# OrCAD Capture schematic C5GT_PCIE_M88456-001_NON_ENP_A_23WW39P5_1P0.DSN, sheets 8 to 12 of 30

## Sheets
8 Clocks & Osc.: size B
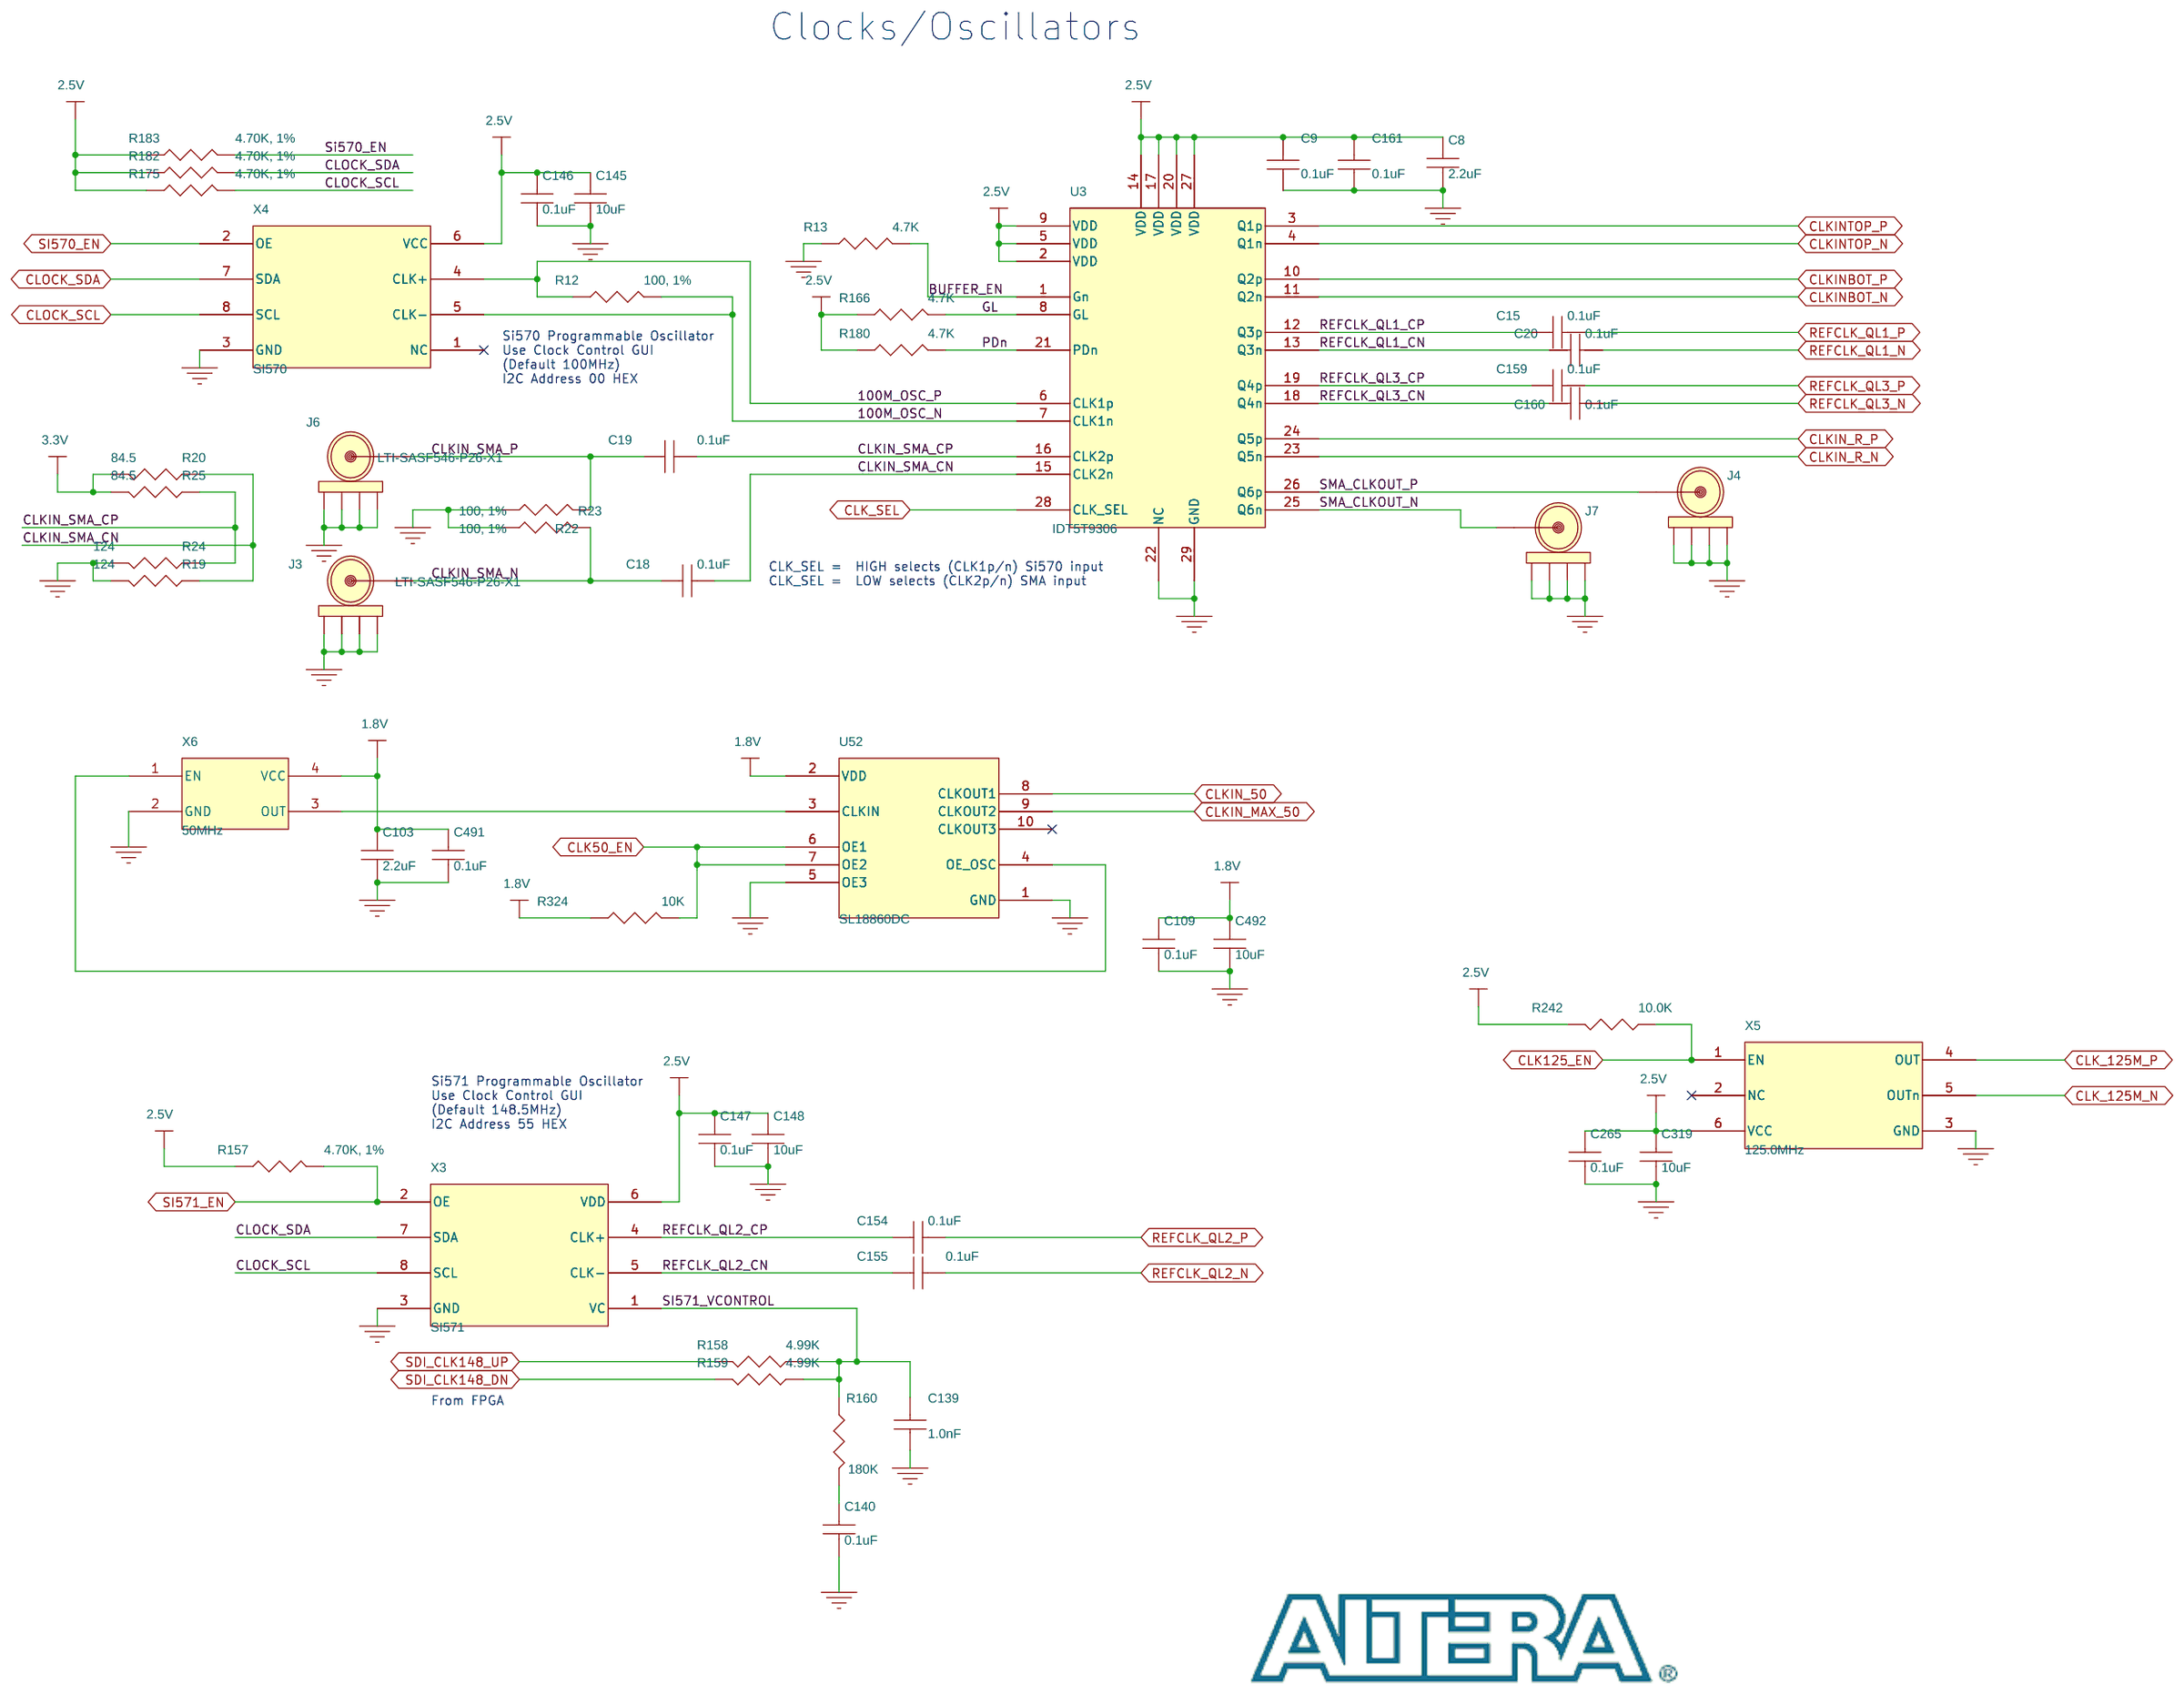
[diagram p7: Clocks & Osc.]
9 Cycone V GT Clks: size B
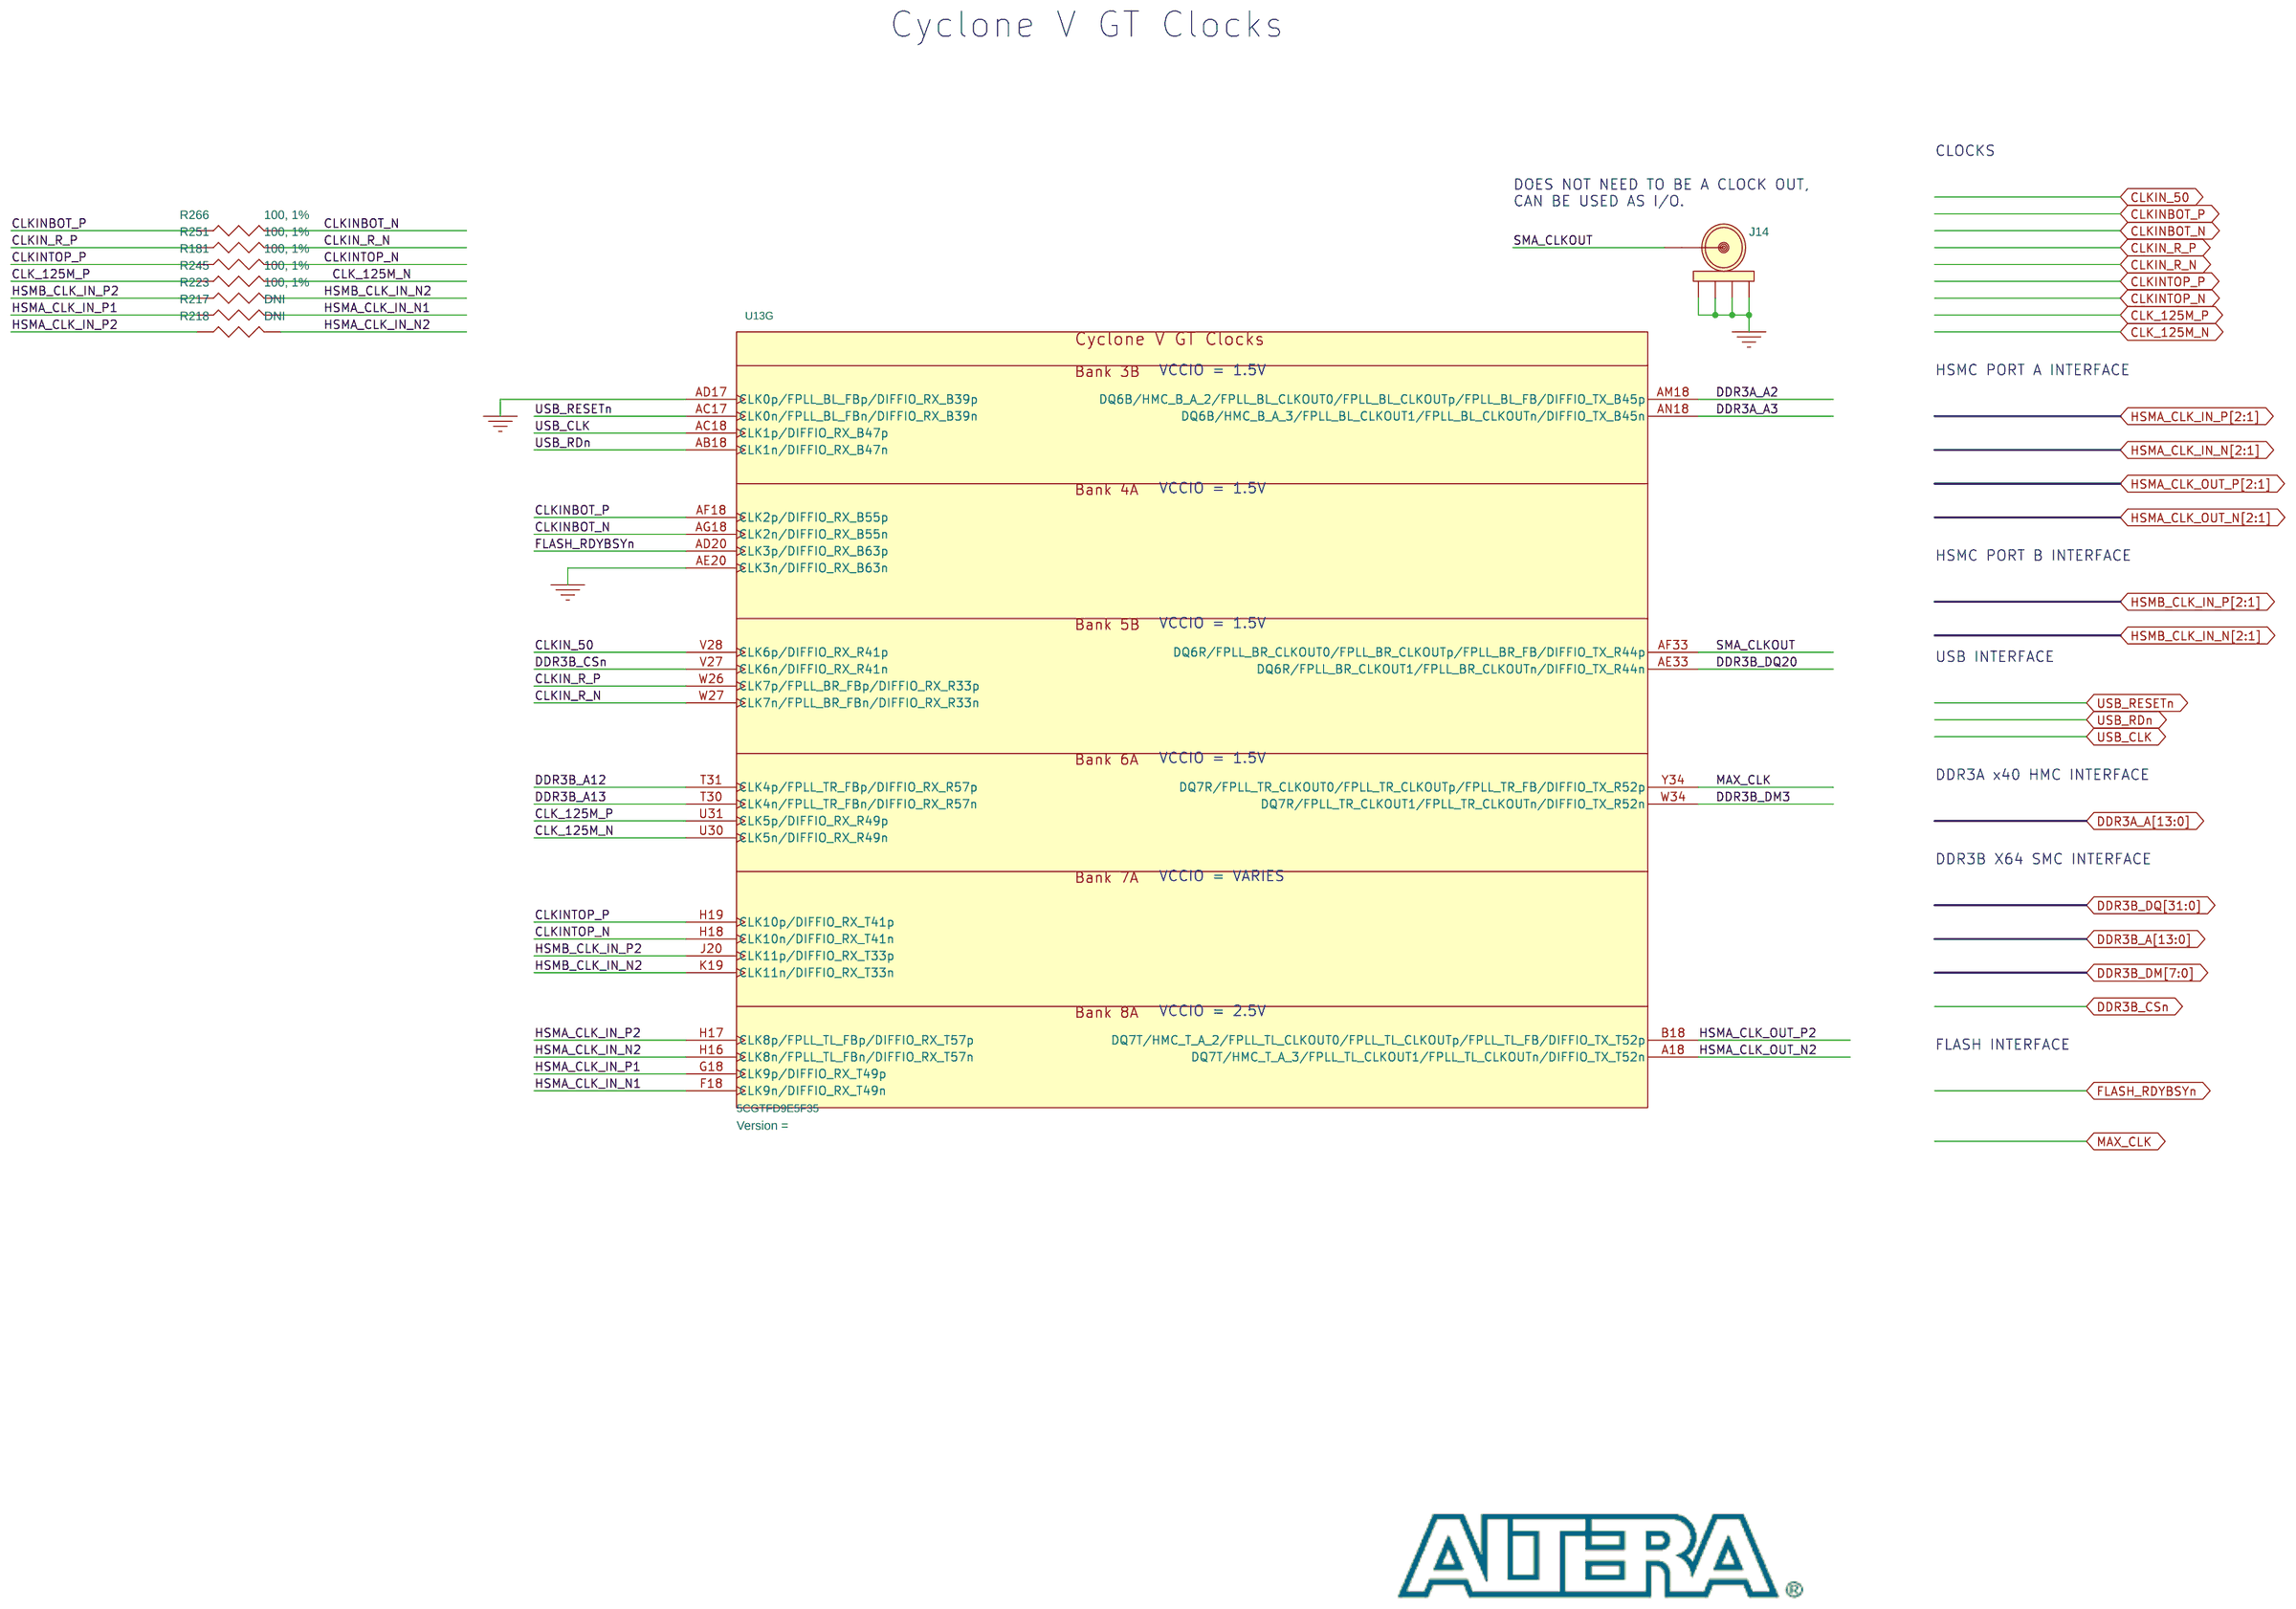
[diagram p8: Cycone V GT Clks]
10 Cycone V GT Config: size B
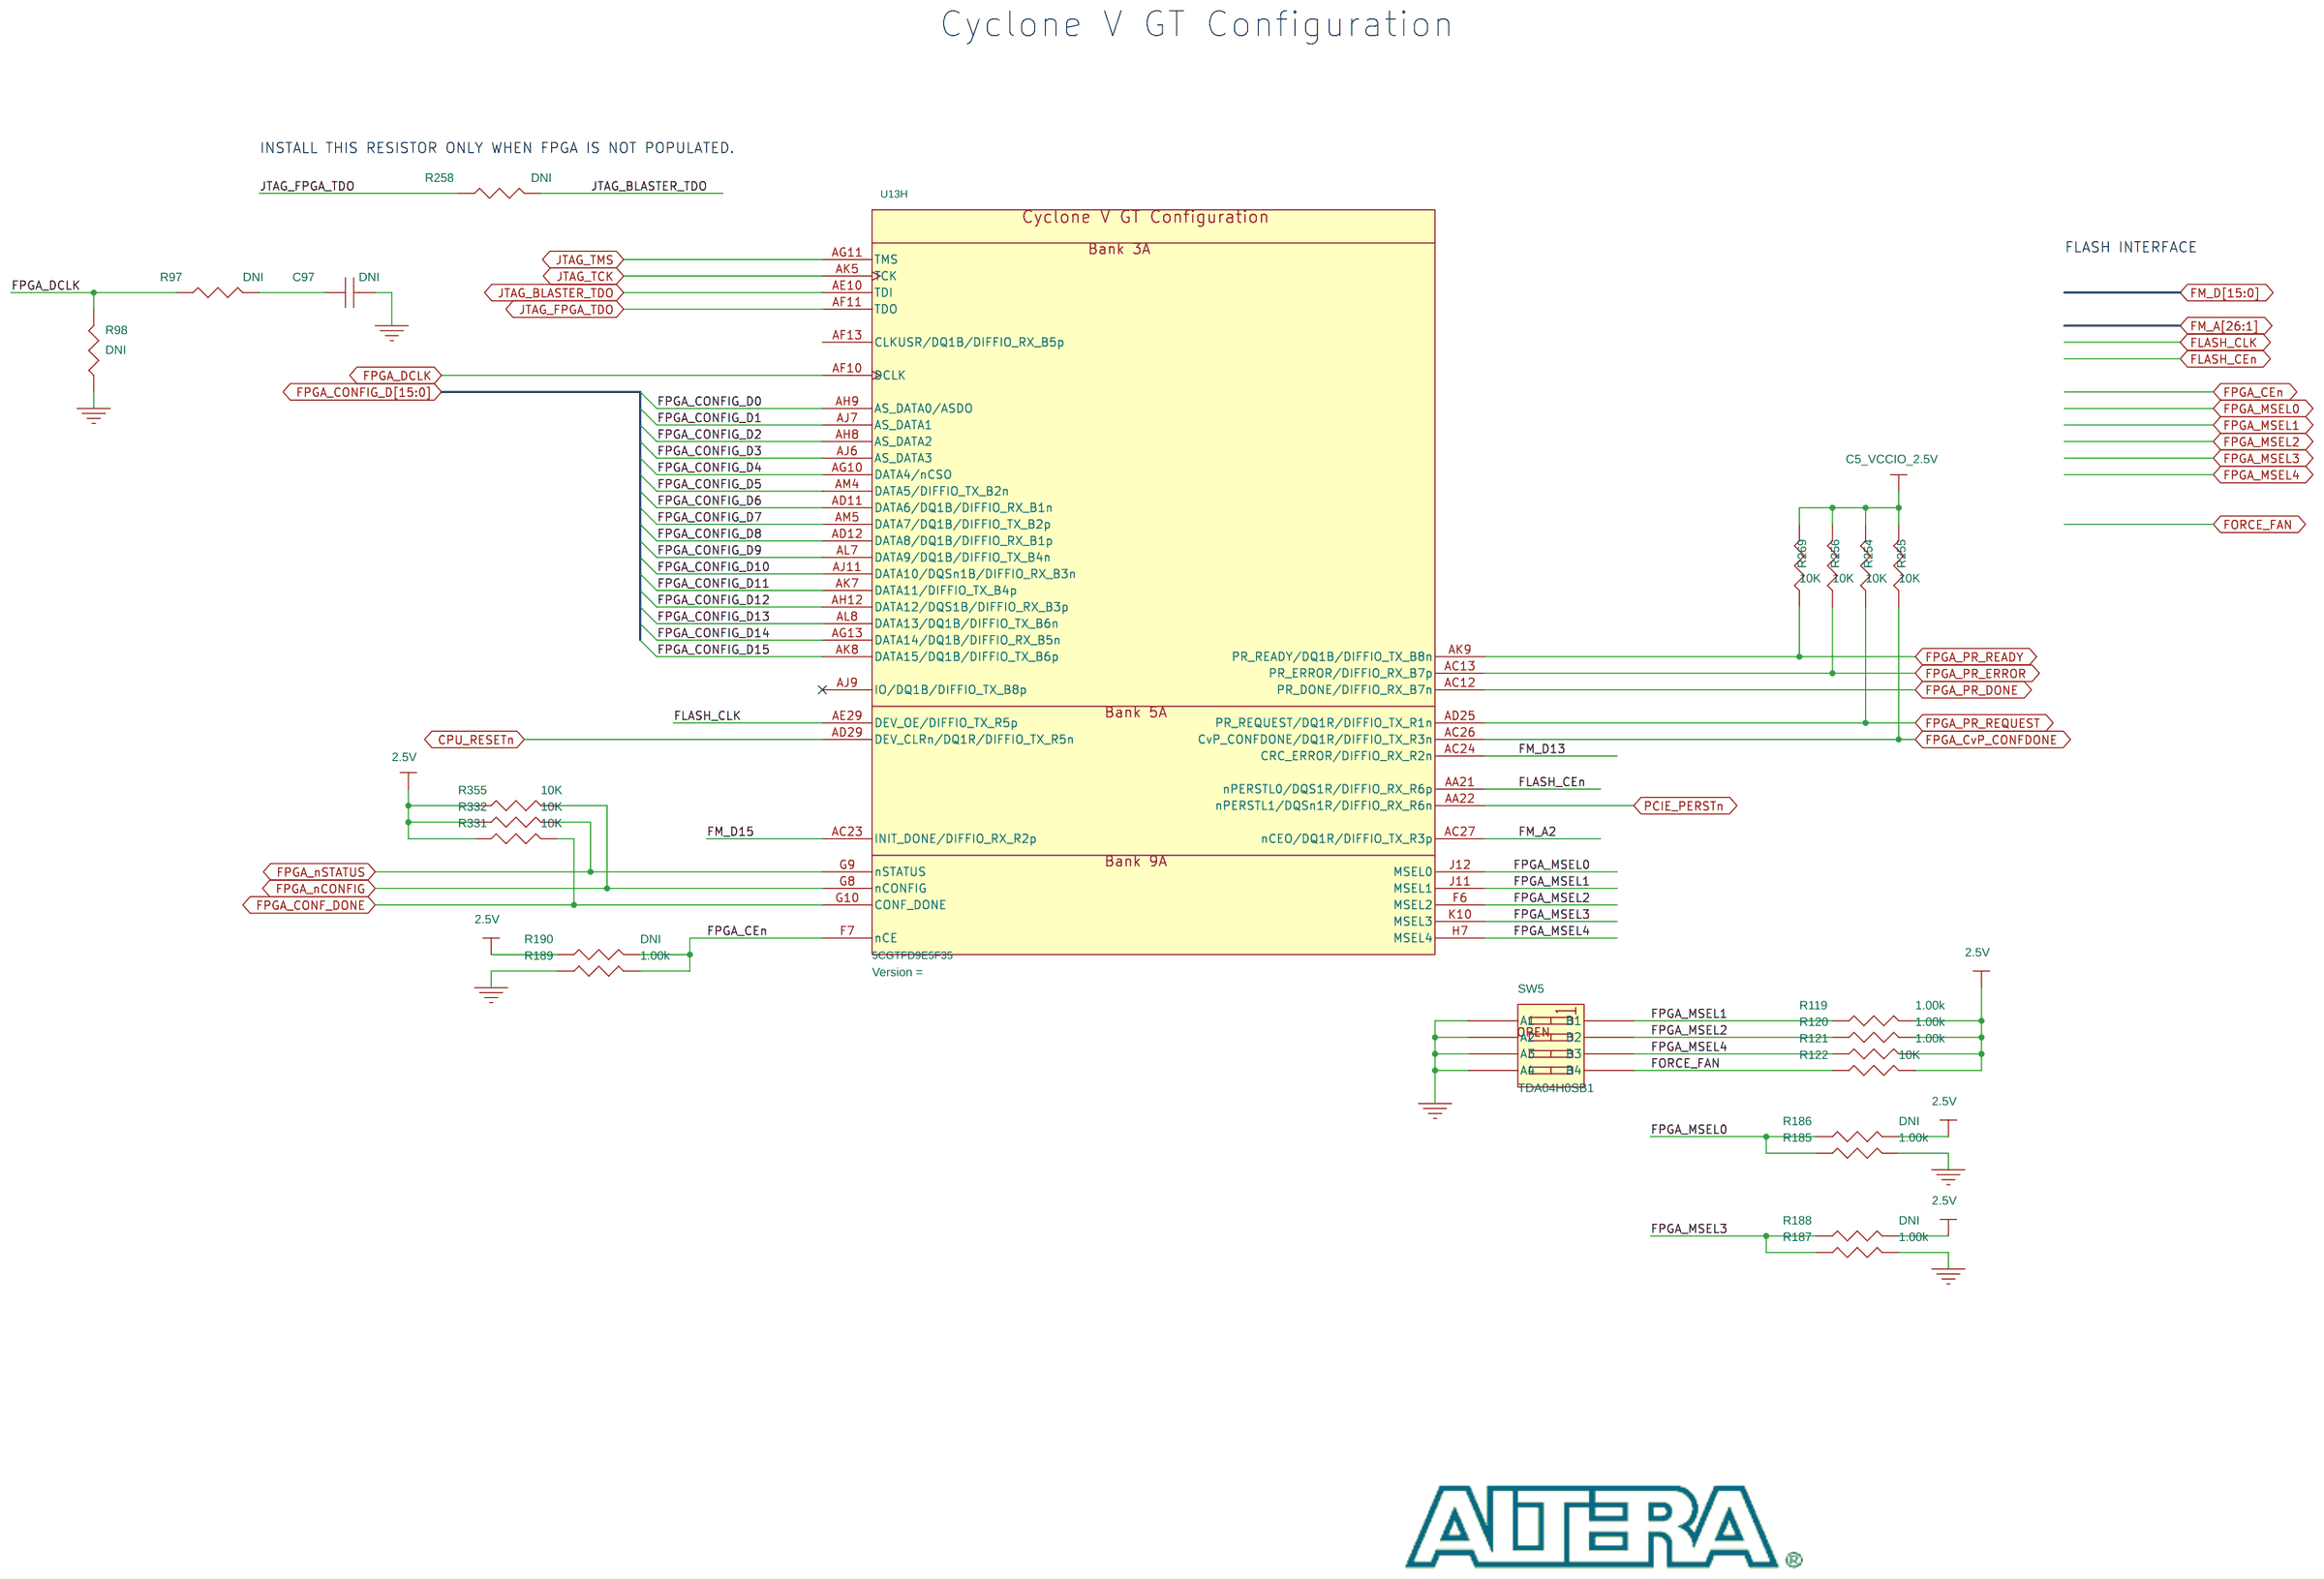
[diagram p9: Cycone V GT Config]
11 JTAG: size B
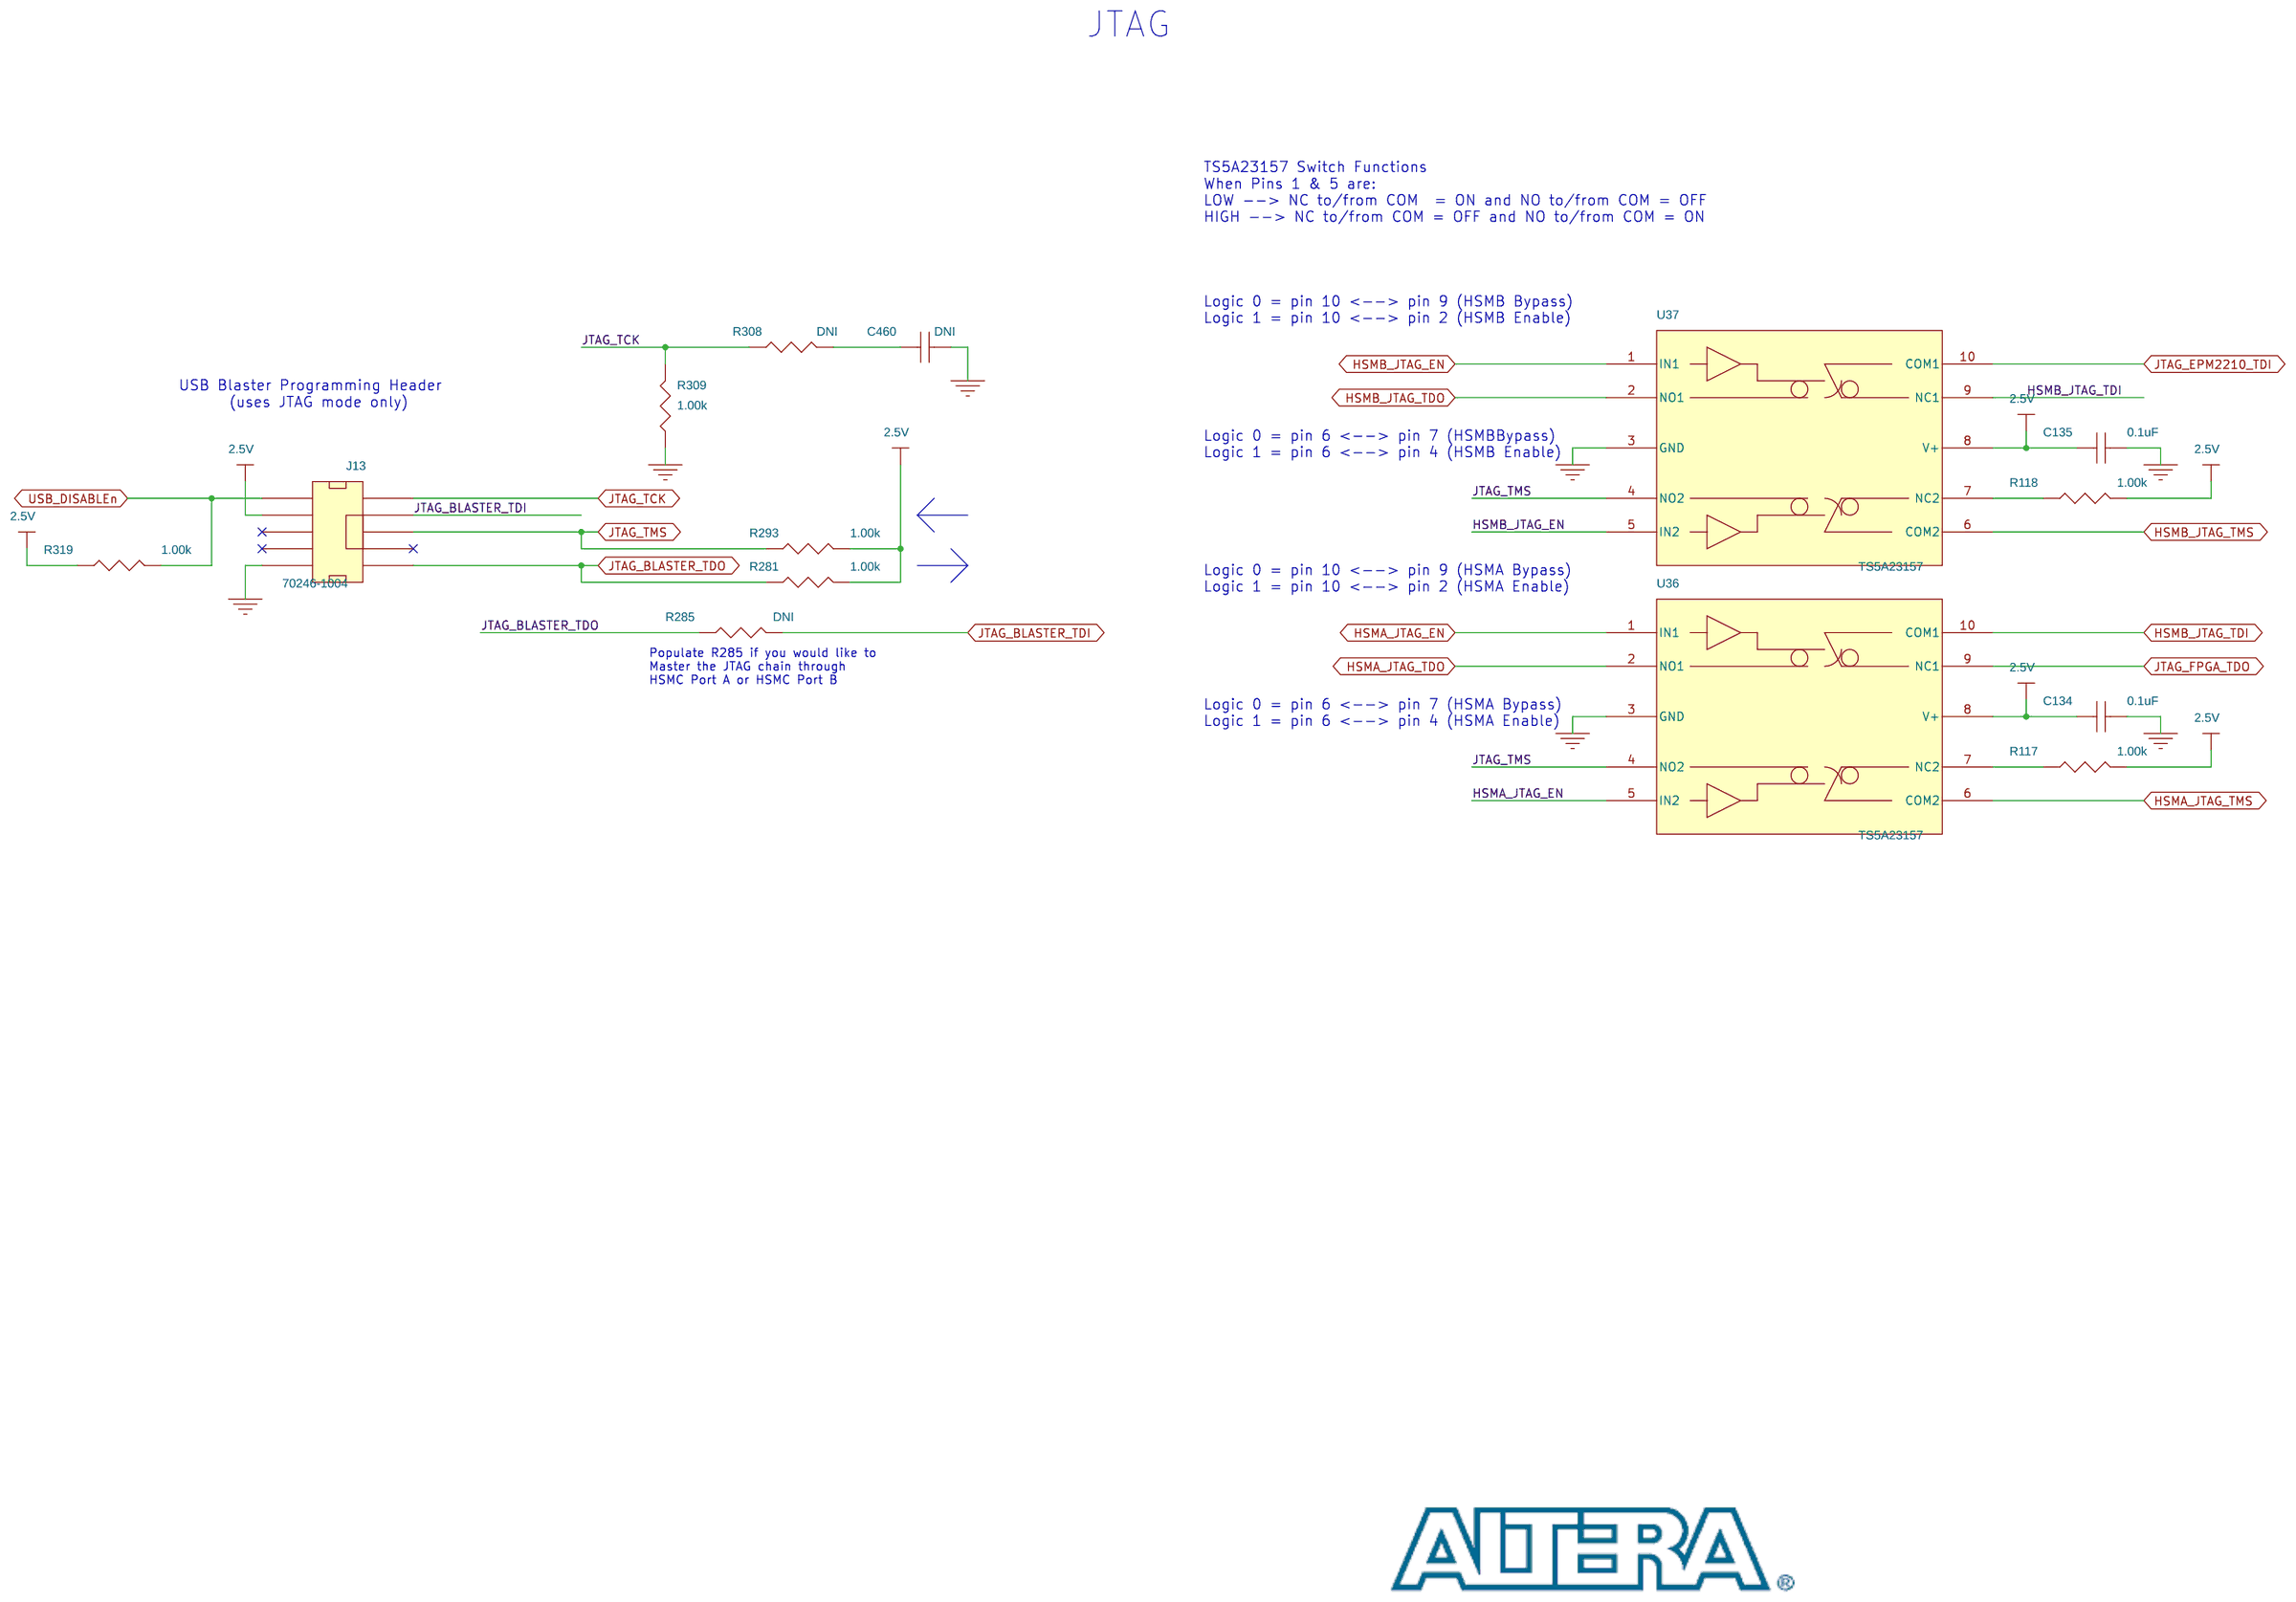
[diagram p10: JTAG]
12 DDR3A - x40 HMC: size B
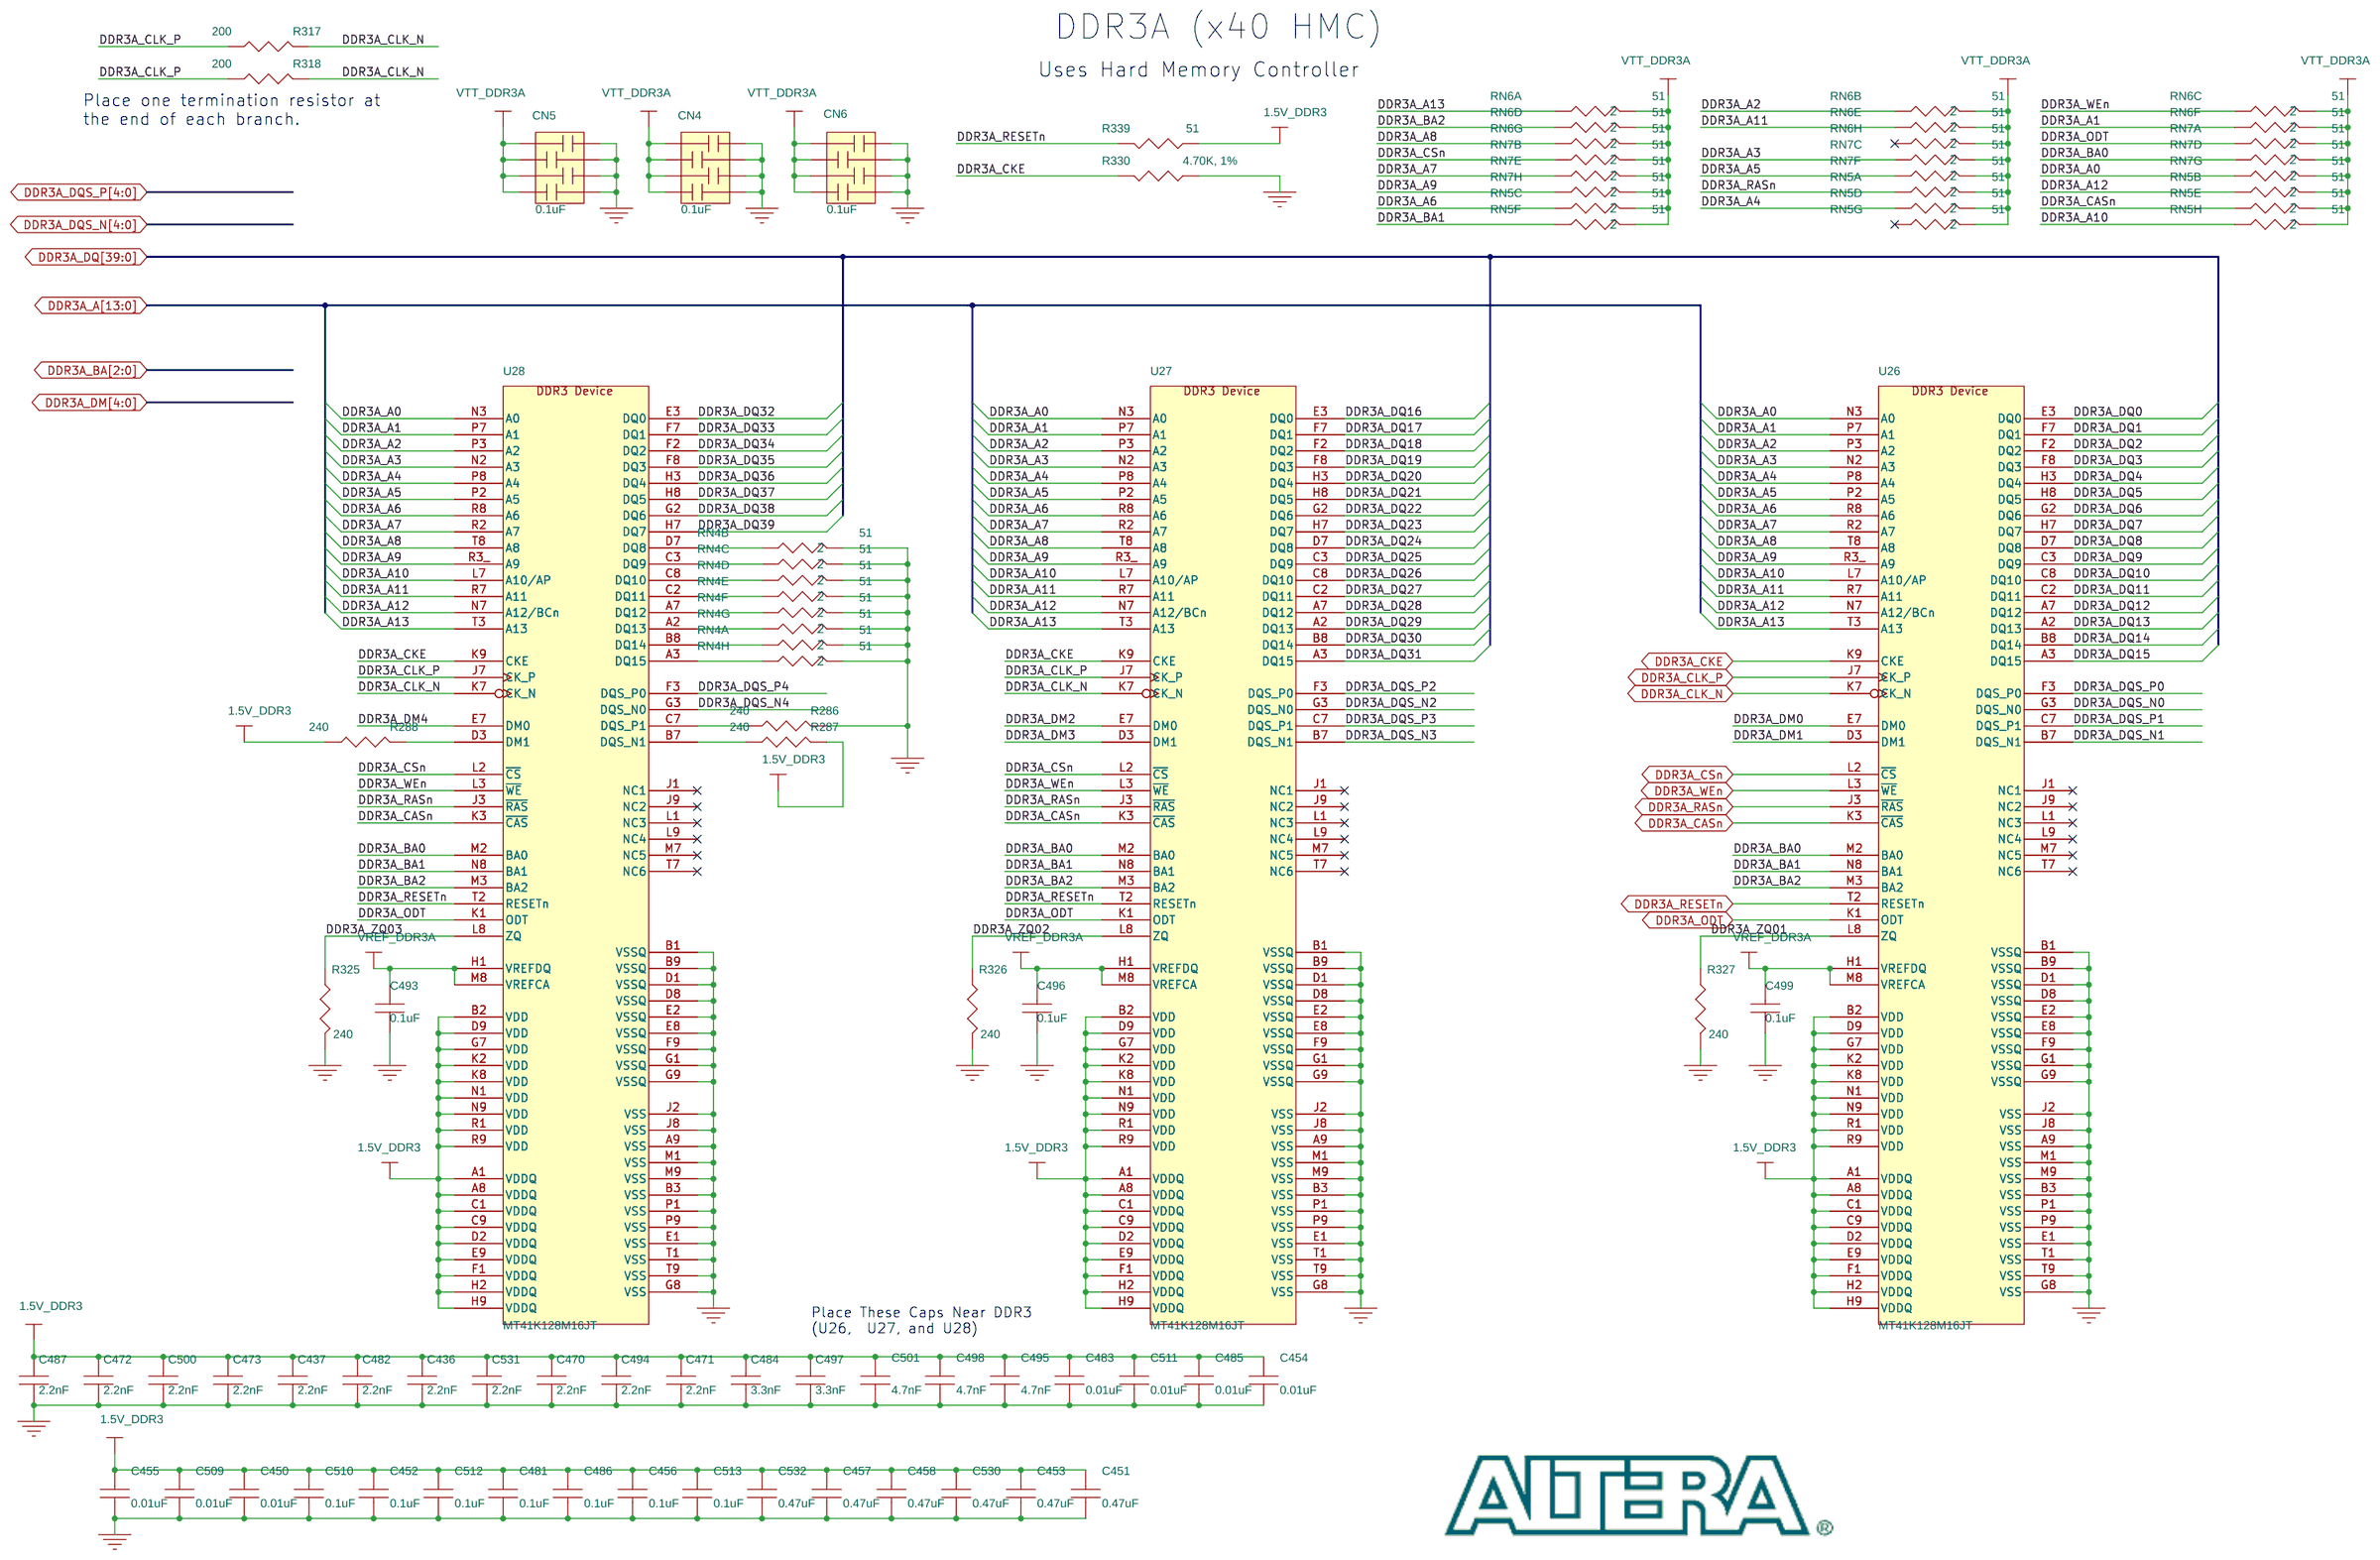
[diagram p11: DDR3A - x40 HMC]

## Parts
sheet Clocks & Osc.
C8  2.2uF  [0603]
C9  0.1uF  [0402]
C15  0.1uF  [0402]
C18  0.1uF  [0402]
C19  0.1uF  [0402]
C20  0.1uF  [0402]
C103  2.2uF  [0603]
C109  0.1uF  [0402]
C139  1.0nF  [0402]
C140  0.1uF  [0402]
C145  10uF  [0805]
C146  0.1uF  [0402]
C147  0.1uF  [0402]
C148  10uF  [0805]
C154  0.1uF  [0402]
C155  0.1uF  [0402]
C159  0.1uF  [0402]
C160  0.1uF  [0402]
C161  0.1uF  [0402]
C265  0.1uF  [0402]
C319  10uF  [0805]
C491  0.1uF  [0402]
C492  10uF  [0805]
J3  LTI-SASF546-P26-X1  [SMA_LTI-SASF546-P26-X1]
J4  LTI-SASF546-P26-X1  [SMA_LTI-SASF546-P26-X1]
J6  LTI-SASF546-P26-X1  [SMA_LTI-SASF546-P26-X1]
J7  LTI-SASF546-P26-X1  [SMA_LTI-SASF546-P26-X1]
R12  100, 1%  [0402]
R13  4.7K  [0402]
R19  124  [0402]
R20  84.5  [0402]
R22  100, 1%  [0402]
R23  100, 1%  [0402]
R24  124  [0402]
R25  84.5  [0402]
R157  4.70K, 1%  [0402]
R158  4.99K  [0402]
R159  4.99K  [0402]
R160  180K  [0402]
R166  4.7K  [0402]
R175  4.70K, 1%  [0402]
R180  4.7K  [0402]
R182  4.70K, 1%  [0402]
R183  4.70K, 1%  [0402]
R242  10.0K  [0402]
R324  10K  [0402]
U3  IDT5T9306  [VFQFPN-28_EPAD]
U52  SL18860DC  [TDFN-10]
X3  SI571  [XTAL_SI570]
X4  SI570  [XTAL_SI570]
X5  125.0MHz  [XTAL_EG2100]
X6  50MHz  [ECS3525]
sheet Cyclone V GT,  XCVRs
U13  5CGTFD9E5F35  [F1152]  (sections A,B,C,D,E,F,G,H,I,J,K,L,M,N,O)
sheet Cycone V GT Clks
J14  LTI-SASF546-P26-X1  [SMA_LTI-SASF546-P26-X1]
R181  100, 1%  [0402]
R217  DNI  [0402]
R218  DNI  [0402]
R223  100, 1%  [0402]
R245  100, 1%  [0402]
R251  100, 1%  [0402]
R266  100, 1%  [0402]
sheet Cycone V GT Config
C97  DNI  [0402]
R97  DNI  [0402]
R98  DNI  [0402]
R119  1.00k  [0402]
R120  1.00k  [0402]
R121  1.00k  [0402]
R122  10K  [0402]
R185  1.00k  [0402]
R186  DNI  [0402]
R187  1.00k  [0402]
R188  DNI  [0402]
R189  1.00k  [0402]
R190  DNI  [0402]
R254  10K  [0402]
R255  10K  [0402]
R256  10K  [0402]
R258  DNI  [0402]
R269  10K  [0402]
R331  10K  [0402]
R332  10K  [0402]
R355  10K  [0402]
SW5  TDA04H0SB1  [DIPSWITCH_SMT_QUAD]
sheet DDR3A - x40 HMC
C436  2.2nF  [0402]
C437  2.2nF  [0402]
C450  0.01uF  [0402]
C451  0.47uF  [0402]
C452  0.1uF  [0402]
C453  0.47uF  [0402]
C454  0.01uF  [0402]
C455  0.01uF  [0402]
C456  0.1uF  [0402]
C457  0.47uF  [0402]
C458  0.47uF  [0402]
C470  2.2nF  [0402]
C471  2.2nF  [0402]
C472  2.2nF  [0402]
C473  2.2nF  [0402]
C481  0.1uF  [0402]
C482  2.2nF  [0402]
C483  0.01uF  [0402]
C484  3.3nF  [0402]
C485  0.01uF  [0402]
C486  0.1uF  [0402]
C487  2.2nF  [0402]
C493  0.1uF  [0402]
C494  2.2nF  [0402]
C495  4.7nF  [0402]
C496  0.1uF  [0402]
C497  3.3nF  [0402]
C498  4.7nF  [0402]
C499  0.1uF  [0402]
C500  2.2nF  [0402]
C501  4.7nF  [0402]
C509  0.01uF  [0402]
C510  0.1uF  [0402]
C511  0.01uF  [0402]
C512  0.1uF  [0402]
C513  0.1uF  [0402]
C530  0.47uF  [0402]
C531  2.2nF  [0402]
C532  0.47uF  [0402]
CN4  0.1uF  [CAP_PACK_4_1206]
CN5  0.1uF  [CAP_PACK_4_1206]
CN6  0.1uF  [CAP_PACK_4_1206]
R286  240  [0402]
R287  240  [0402]
R288  240  [0402]
R317  200  [0402]
R318  200  [0402]
R325  240  [0402]
R326  240  [0402]
R327  240  [0402]
R330  4.70K, 1%  [0402]
R339  51  [0402]
RN4  51  [RES_PACK_8]  (sections A,B,C,D,E,F,G,H)
RN5  51  [RES_PACK_8]  (sections A,B,C,D,E,F,G,H)
RN6  51  [RES_PACK_8]  (sections A,B,C,D,E,F,G,H)
RN7  51  [RES_PACK_8]  (sections A,B,C,D,E,F,G,H)
U26  MT41K128M16JT  [Micron_ddr3_96_9x14]
U27  MT41K128M16JT  [Micron_ddr3_96_9x14]
U28  MT41K128M16JT  [Micron_ddr3_96_9x14]
sheet JTAG
C134  0.1uF  [0402]
C135  0.1uF  [0402]
C460  DNI  [0402]
J13  70246-1004  [MLX_SHROUD_VRT_HDR_10PIN]
R117  1.00k  [0402]
R118  1.00k  [0402]
R281  1.00k  [0402]
R285  DNI  [0402]
R293  1.00k  [0402]
R308  DNI  [0402]
R309  1.00k  [0402]
R319  1.00k  [0402]
U36  TS5A23157  [MSOP10]
U37  TS5A23157  [MSOP10]

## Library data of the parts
C8 C103 = CAP: CAP, CERAMIC, 2.2UF, 10%, 10VDC, X5R, 0603; AGILE_LINK: http://sj-agile9app/Agile/PLMServlet?action=OpenEmailObject&classid=10000&objid=256999866; IPN: M97320-001; Item Num: P03-15213R; LIFECYCLE_PHASE: Active; Lead Free Status: Lead Free; MFR_LIFECYCLE: Active; Manufacturer: Murata; Manufacturer Part Num: GRM188R61A225KE34x; Num Pins: 2; PART_SUBCLASS: CAPACITORS; RATED_VOLTAGE: 10V; RoHS Compliant: RoHS Compliant; Supplier Part Num: 490-1545-1-ND; TOLERANCE: +/-10%
C9 C15 C18-C20 C109 C140 C146 C147 C154 C155 C159-C161 C265 C491 C496 C499 = CAP: CAP - CERAMIC,  0.1UF 0402 25VDC Y5V; AGILE_LINK: http://sj-agile9app/Agile/PLMServlet?action=OpenEmailObject&classid=10000&objid=213459527; IPN: K13560-001; Item Num: P03-15057R; LIFECYCLE_PHASE: Active; Lead Free Status: Lead Free; MFR_LIFECYCLE: Active; Manufacturer: Murata; Manufacturer Part Num: GRM155F51E104ZA01D; Num Pins: 2; PART_SUBCLASS: CAPACITORS; Part Class: CAPACITORS; RATED_VOLTAGE: 25V; RoHS Compliant: RoHS Compliant; TOLERANCE: +80%/-20%
C139 = CAP: CAP - CER, 1NF, 10%, 50V, X7R, 0402; AGILE_LINK: http://sj-agile9app/Agile/PLMServlet?action=OpenEmailObject&classid=10000&objid=256956561; IPN: D62711-001; Item Num: P03-15174R; LIFECYCLE_PHASE: Active; MFR_LIFECYCLE: Active; Manufacturer: Murata; Manufacturer Part Num: GRM155R71H102KA01D; Num Pins: 2; PART_SUBCLASS: CAPACITORS; RATED_VOLTAGE: 50V; RoHS Compliant: RoHS Compliant; TOLERANCE: +/-10%
C145 C148 C319 C492 = CAP: CAP, CERAMIC, 10UF, 10%, 6.3V, X5R, 0805; AGILE_LINK: http://sj-agile9app/Agile/PLMServlet?action=OpenEmailObject&classid=10000&objid=256999279; IPN: K13567-001; Item Num: P03-15212R; LIFECYCLE_PHASE: Active; Lead Free Status: Lead Free; MFR_LIFECYCLE: Active; Manufacturer: Murata; Manufacturer Part Num: GRM219R60J106KE19x; Num Pins: 2; PART_SUBCLASS: CAPACITORS; RATED_VOLTAGE: 6.3V; RoHS Compliant: RoHS Compliant; Supplier Part Num: 490-3340-1-ND; TOLERANCE: +/-10%
J3 J6 = SMA_LTI_SASF54GT_0: CONN -  SMA VERTICAL GOLD PLATED SMT CENTER CONDUCTOR; IPN: K10975-001; Item Num: P23-35090R; Lead Free Status: No; Manufacturer: Lighthorse Technologies Inc.; Num Pins: 5; Part Class: Connectors; Price: 1.93; RoHS Compliant: Yes
J4 J7 J14 = SMA: CONN -  SMA VERTICAL GOLD PLATED SMT CENTER CONDUCTOR; IPN: K10975-001; Item Num: P23-35090R; Lead Free Status: No; Manufacturer: Lighthorse Technologies Inc.; Num Pins: 5; Part Class: Connectors; Price: 1.93; RoHS Compliant: Yes
R12 R22 R23 = RESISTOR: RES,100 OHMS,1.0%,1/16W,0402; IPN: A36092-043; Item Num: P02-11381R; Lead Free Status: No; Manufacturer: Panasonic; Manufacturer Part Num: ERJ-2RKF1000X; Num Pins: 2; Part Class: RESISTORS; Price: 0; RoHS Compliant: Yes; Tolerance: 1%
R13 R166 R180 = RESISTOR: RES 4.7K OHM 1/16W 5% 0402 SMD; IPN: A93549-020; Item Num: P02-14032R; Lead Free Status: No; Manufacturer: Panasonic; Manufacturer Part Num: ERJ-2GEJ472X; Manufacturer's Part No.: ERJ-2GEJ472X; Num Pins: 2; Part Class: RESISTORS; Price: 0; RoHS Compliant: Yes
R19 R24 = RESISTOR: RES - 124 OHM 1/16W 1% 0402 SMD; AGILE_LINK: http://sj-agile9app/Agile/PLMServlet?action=OpenEmailObject&classid=10000&objid=210536060; IPN: K15715-001; Item Num: P02-14065R; LIFECYCLE_PHASE: Active; Lead Free Status: Lead Free; MFR_LIFECYCLE: Active; Manufacturer: Panasonic; Manufacturer Part Num: ERJ-2RKF1240X; Num Pins: 2; PACKAGING: Tape & Reel (TR); PART_SUBCLASS: RESISTORS; POWER: 1/16W; RoHS Compliant: RoHS Compliant; SUPPLIER_PART_NO: ERJ-2RKF1240X; TOLERANCE: +/-1%; UNIT_PRICE: .007
R20 R25 = RESISTOR: RES, 84.5 OHMS, 1%, 1/16W, 0402; AGILE_LINK: http://sj-agile9app/Agile/PLMServlet?action=OpenEmailObject&classid=10000&objid=218075914; IPN: K15617-001; Item Num: P02-14104R; LIFECYCLE_PHASE: Active; MFR_LIFECYCLE: Active; Manufacturer: Panasonic; Manufacturer Part Num: ERJ-2RKF84R5X; Num Pins: 2; PART_SUBCLASS: RESISTORS; POWER: 1/16W; RoHS Compliant: RoHS Compliant; TOLERANCE: +/-1%
R157 R175 R182 R183 R330 = RESISTOR: RES,4.70K OHMS,1.0%,1/16W,0402; AGILE_LINK: http://sj-agile9app/Agile/PLMServlet?action=OpenEmailObject&classid=10000&objid=146753272; IPN: A93548-517; Item Num: P02-11384R; LIFECYCLE_PHASE: Active; MFR_LIFECYCLE: Active; Manufacturer: Vishay; Manufacturer Part Num: CRCW04024K70FKED; Num Pins: 2; PART_SUBCLASS: RESISTORS; POWER: 1/16W; RESISTANCE: 4.7K; TOLERANCE: +/-1%
R158 R159 = RESISTOR: RES 4.99K OHM 1/16W 1% 0402 SMD; IPN: A78616-001; Item Num: P02-14129R; Lead Free Status: Yes; Manufacturer: Panasonic; Manufacturer Part Num: ERJ-2RKF4991X; Num Pins: 2; Part Class: Resistors; Price: 0
R160 = RESISTOR: RES, 180 KOHM 1/16W 1% 0402 SMD; AGILE_LINK: http://sj-agile9app/Agile/PLMServlet?action=OpenEmailObject&classid=10000&objid=239318010; IPN: A93548-479; Item Num: P02-14144R; LIFECYCLE_PHASE: Active; MFR_LIFECYCLE: Active; Manufacturer: Yageo America/Phycomp; Manufacturer Part Num: RC0402FR-07180KL; Num Pins: 2; PACKAGING: Tape & Reel (TR); PART_SUBCLASS: RESISTORS; POWER: 1/16W; RoHS Compliant: RoHS Compliant; SUPPLIER_PART_NO: 311-180KLRCT-ND (DIGI-KEY); TOLERANCE: +/-1%
R242 = RESISTOR: RES,10.0K OHMS,1.0%,1/16W, 0402; AGILE_LINK: http://sj-agile9app/Agile/PLMServlet?action=OpenEmailObject&classid=10000&objid=146548997; IPN: A93548-034; Item Num: P02-11364R; LIFECYCLE_PHASE: Active; Lead Free Status: No; MFR_LIFECYCLE: Active; Manufacturer: Panasonic; Manufacturer Part Num: ERJ-2RKF1002X; Num Pins: 2; PART_SUBCLASS: RESISTORS; POWER: 1/16W; RESISTANCE: 10K; RoHS Compliant: Yes; TOLERANCE: +/-1%
R122 R324 = RESISTOR: RES 10K OHM 1/16W 5% 0402 SMD; IPN: D83138-001; Item Num: P02-14023R; Lead Free Status: No; Manufacturer: Panasonic; Manufacturer Part Num: ERJ-2GEJ103X; Num Pins: 2; Part Class: RESISTORS; Price: 0; RoHS Compliant: Yes
U3 = IDT5T9306_0: IC - DIFF TO LVDS CLOCK BUFFER LOW SKEW 2 TO 6; IPN: H37996-001; Item Num: P01-15765R; Manufacturer: IDT; Manufacturer Part Num: 5T9306NLGI; Manufacturer's Part No.: 5T9306NLGI; Num Pins: 29; Part Class: IC; RoHS Compliant: YES
U52 = SL18860DC: IC - 1:3 Clock Buffer, 10 to 52MHz, VDD=1.7V - 3.65V,10-pin TDFN; IPN: K13851-001; Item Num: P01-17717R; Manufacturer: Silicon Labs
X3 = SI571: OSC - 10-810MHZ VCXO, 2.5V, LVDS, DEFAULT 148.5MHZ, SMT 5.0MM X 7.5MM, +/-50PPM; IPN: J43864-001; Item Num: P13-27190R; Manufacturer: Silicon Laboratories; Manufacturer Part Num: 571FDB000159DG
X4 = SI570_ALT1: OSC - 10-810MHZ XO, 2.5V, SMT 5.0MM X 7.5MM, +/-50PPM; IPN: K14751-001; Item Num: P13-26850R; Manufacturer: Silicon Laboratories; Manufacturer Part Num: 570FAB000433DG
X5 = 635L3C3: CRYSTAL, 125.000MHZ SAW OSC, LVDS, 2.5V, SMT 5.0MM X 7.5MM, +/-50PPM; IPN: N21405-001; Item Num: P07-19189R; Manufacturer: EPSON Toyocom; Manufacturer Part Num: SIT9120AI-2DF-25E125.0000
X6 = OSC_ALT_0: : OSC - 50MHZ, +/-50PPM, 1.8V, CLOCK OSCILLATOR, SMD (5 X 3.2) MM; IPN: K14746-001; Item Num: P13-26930R; Lead Free Status: Yes; Manufacturer: ECS, Inc.; Manufacturer Part Num: ECS-3518-500-B-xx; Num Pins: 4; Part Class: Oscillators; RoHS Compliant: Yes
U13 = 5CGTFD9E5F35: IC - FPGA, Cyclone V GT F1152, 301K LEs, (35x35)mm BGA, leadfree; Created by: pmurray; Date: 10/29/12; IPN: 965959; Item Num: P01-17810R; Manufacturer: Altera; Manufacturer Part Num: 5CGTFD9E5F35C7N
R181 R217 R218 R223 R245 R251 R266 = RESISTOR: RES,100 OHMS,1.0%,1/16W,0402; IPN: A36092-043; Item Num: P02-11381R; Lead Free Status: No; Manufacturer: Panasonic; Manufacturer Part Num: ERJ-2RKF1000X; Num Pins: 2; Part Class: Resistors; Price: 0; RoHS Compliant: Yes; Tolerance: 1%
C97 C460 = CAP: CAP - CERAMIC,  0.1UF 0402 25VDC Y5V; Dielectric: Y5V; IPN: K13560-001; Item Num: P03-15057R; Lead Free Status: Yes; Manufacturer: Murata; Manufacturer Part Num: GRM155F51E104ZA01D; Num Pins: 2; Part Class: CAPACITORS; Price: 0.07; RoHS Compliant: Yes; Tolerance: 10%
R97 R308 = RESISTOR: RES,10.0K OHMS,1.0%,1/16W, 0402; IPN: A93548-034; Item Num: P02-11364R; Lead Free Status: No; Manufacturer: Panasonic; Manufacturer Part Num: ERJ-2RKF1002X; Num Pins: 2; Part Class: Resistors; Price: 0; RoHS Compliant: Yes
R98 R117-R121 R185-R190 R281 R293 R309 R319 = RESISTOR: RES,1.00K OHMS,1.0%,1/16W,0402; IPN: G60609-021; Item Num: P02-11372R; Lead Free Status: No; Manufacturer: Panasonic; Manufacturer Part Num: ERJ-2RKF1001X; Num Pins: 2; Part Class: Resistors
R254-R256 R269 R331 R332 R355 = RESISTOR: RES 10K OHM 1/16W 5% 0402 SMD; IPN: D83138-001; Item Num: P02-14023R; Lead Free Status: No; Manufacturer: Panasonic; Manufacturer Part Num: ERJ-2GEJ103X; Manufacturer's Part No.: ERJ-2GEJ103X; Num Pins: 2; Part Class: RESISTORS; Price: 0; RoHS Compliant: Yes
R258 R285 = RESISTOR: RES ZERO OHM 1/16W 5% 0402 SMD; Altera Part No.: P02-14020R; IPN: A93549-001; Item Num: P02-14020R; Lead Free Status: No; Manufacturer: Panasonic; Manufacturer Part Num: ERJ-2GE0R00X; Num Pins: 2; Part Class: RESISTORS; Price: 0; RoHS Compliant: Yes; Tolerance: 5%
SW5 = SPST4: SWITCHES - 4 POS, 8 PIN, Ultra-mini SMT Half-pitch Slider DIP Switch; AGILE_LINK: http://sj-agile9app/Agile/PLMServlet?action=OpenEmailObject&classid=10000&objid=258073635; IPN: A35353-010; Item Num: P11-24098R; LIFECYCLE_PHASE: Preliminary; Lead Free Status: Not Lead Free; MFR_LIFECYCLE: Active; Manufacturer: C & K Components/ITT Industries; Num Pins: 8; PART_SUBCLASS: SWITCHES; RoHS Compliant: RoHS Compliant
C436 C437 C470-C473 C482 C487 C494 C500 C531 = CAP: CAP CER 2200PF 50V 10% X7R 0402; AGILE_LINK: http://sj-agile9app/Agile/PLMServlet?action=OpenEmailObject&classid=10000&objid=204246494; CAPACITANCE: 2200pF; IPN: A36096-022; Item Num: P03-15048R; LIFECYCLE_PHASE: Active; Manufacturer: Murata; Manufacturer Part Num: GRM155R71H222KA01D; Num Pins: 2; PART_SUBCLASS: CAPACITORS; RATED_VOLTAGE: 50V; TOLERANCE: +/-10%
C450 C454 C455 C483 C485 C509 C511 = CAP: CAP, CER .01UF 16V X7R 0402; IPN: A36096-007; Item Num: P03-15137R; Lead Free Status: No; Manufacturer: Murata; Manufacturer Part Num: GRM155R71C103KA01D; Manufacturer's Part No.: GRM155R71C103KA01D; Num Pins: 2; Part Class: CAPACITORS; Price: 0; RoHS Compliant: Yes
C451 C453 C457 C458 C530 C532 = CAP: CAP - CER, 0.47UF, -20% +80%, 10V, Y5V, 0402; AGILE_LINK: http://sj-agile9app/Agile/PLMServlet?action=OpenEmailObject&classid=10000&objid=256989651; IPN: H94452-001; Item Num: P03-15192R; LIFECYCLE_PHASE: Active; Lead Free Status: Lead Free; MFR_LIFECYCLE: Active; Manufacturer: Murata; Manufacturer Part Num: GRM155F51A474ZE01x; Num Pins: 2; PART_SUBCLASS: CAPACITORS; Part Class: CAPACITORS; RATED_VOLTAGE: 10V; RoHS Compliant: RoHS Compliant; Supplier Part Num: 490-3276-1-ND; Tolerance: +80%/-20%
C452 C456 C481 C486 C510 C512 C513 = CAP: CAP - CERAMIC,  0.1UF 0402 25VDC Y5V; Dielectric: X5R; IPN: K13560-001; Item Num: P03-15057R; LIFECYCLE_PHASE: Active; Lead Free Status: Lead Free; Manufacturer: Murata; Manufacturer Part Num: GRM155F51E104ZA01D; Num Pins: 2; Part Class: CAPACITORS; Price: 0.07; RoHS Compliant: RoHS Compliant; Tolerance: +80%/-20%
C484 C497 = CAP: CAP, CERAMIC, 3300PF, 10%, 50V, X7R, 0402; AGILE_LINK: http://sj-agile9app/Agile/PLMServlet?action=OpenEmailObject&classid=10000&objid=257002141; IPN: K13754-001; Item Num: P03-15215R; LIFECYCLE_PHASE: Active; Lead Free Status: Lead Free; MFR_LIFECYCLE: Active; Manufacturer: Murata; Manufacturer Part Num: GRM155F51H332ZA01x; Num Pins: 2; PART_SUBCLASS: CAPACITORS; RATED_VOLTAGE: 50V; RoHS Compliant: RoHS Compliant; TOLERANCE: +/-10%
C493 = CAP: CAP - CERAMIC,  0.1UF 0402 25VDC Y5V; AGILE_LINK: http://sj-agile9app/Agile/PLMServlet?action=OpenEmailObject&classid=10000&objid=213459527; IPN: K13560-001; Item Num: P03-15057R; LIFECYCLE_PHASE: Active; Lead Free Status: Lead Free; MFR_LIFECYCLE: Active; Manufacturer: Murata; Manufacturer Part Num: GRM155F51E104ZA01D; Num Pins: 2; PART_SUBCLASS: CAPACITORS; Part Class: CAPACITORS; RATED_VOLTAGE: 25V; RoHS Compliant: RoHS Compliant
C495 C498 C501 = CAP: CAP - CER 4700PF 50V 10% X7R 0402; AGILE_LINK: http://sj-agile9app/Agile/PLMServlet?action=OpenEmailObject&classid=10000&objid=215384813; IPN: A36096-066; Item Num: P03-15074R; LIFECYCLE_PHASE: Active; Lead Free Status: Lead Free; MFR_LIFECYCLE: Active; Manufacturer: Murata; Manufacturer Part Num: GRM155R71H472KA01D; Num Pins: 2; PACKAGING: Tape & Reel (TR); PART_SUBCLASS: CAPACITORS; RATED_VOLTAGE: 50V; RoHS Compliant: RoHS Compliant; Supplier Part Num: GRM155R71H472KA01D; Tolerance: +/-10%
CN4-CN6 = CAP_ARRAY: CAPNET, 4 CAPS, CERAMIC, 0.1uF, 1206, 20%, 16VDC, X7R; IPN: M97316-001; Item Num: P03-11419R; Manufacturer: Panasonic; Manufacturer Part Num: ECJ-RVB1C104M
R286-R288 R325-R327 = RESISTOR: RES, 240 OHMS, 5%, 1/16W, 0402; AGILE_LINK: http://sj-agile9app/Agile/PLMServlet?action=OpenEmailObject&classid=10000&objid=258528063; IPN: K15734-001; Item Num: P02-15068R; LIFECYCLE_PHASE: Active; Lead Free Status: Lead Free; MFR_LIFECYCLE: Active; Manufacturer: Panasonic; Manufacturer Part Num: ERJ-2GEJ241x; Num Pins: 2; PART_SUBCLASS: RESISTORS; RoHS Compliant: RoHS Compliant
R317 R318 = RESISTOR: RES, 200 OHMS, 1.0%, 1/16W, 0402; IPN: A93548-060; Item Num: P02-10716R; Lead Free Status: No; Manufacturer: Panasonic; Manufacturer Part Num: ERJ-2RKF2000x; Num Pins: 2; Part Class: RESISTORS; Price: 0; RoHS Compliant: Yes; Tolerance: 1%
R339 = RESISTOR: RES, 51 OHMS, 5%, 1/10W, 0402; IPN: K15861-001; Item Num: P02-16891R; Lead Free Status: Yes; Manufacturer: Panasonic; Manufacturer Part Num: ERJ-2GEJ510X; Num Pins: 2; Part Class: Resistors; Price: 0
RN4-RN7 = RES_PACK_0: RESNET - 51 OHM, 5%, 0.25W, 8-0402 RESISTORS,(3.8X1.6)MM, SMD; IPN: J41779-001; Item Num: P02-16648R; Lead Free Status: Yes; Manufacturer Part Num: EXB-2HV510JV; Manufacturer's Part No.: EXB-2HV510JV; Num Pins: 16; Part Class: RESISTORS; Price: 0; RoHS Compliant: Yes
U26-U28 = MT41J128M16HA: IC - DRAM, DDR3, 16MX16X8, 2Gb, CL11, ON-DIE-TERMINATION, 1.35/1.5V CORE/IO,533MHz. BGA-96, LEAD-FREE; IPN: K13937-001; Item Num: P01-17809R; Manufacturer: Micron; Manufacturer Part Num: MT41K128M16JT-125
C134 C135 = CAP: CAP, CERAMIC, 0.1uF, 10%, 10VDC, 0402, X5R; IPN: A36096-009; Item Num: P03-15030R; LIFECYCLE_PHASE: Active; Lead Free Status: Lead Free; Manufacturer: Panasonic; Manufacturer Part Num: ECJ-0EB1A104K; Num Pins: 2; Part Class: CAPACITORS; Price: 0; RoHS Compliant: RoHS Compliant
J13 = 70247-1051: CONN, HEADER SHROUDED, RECPT, VERTICAL, TH, 100MIL, 2X5, 10 PIN; IPN: K12134-001; Item Num: P23-35029R; Lead Free Status: No; Manufacturer: Molex; Num Pins: 10; Part Class: Connectors; Price: 1; RoHS Compliant: Yes
U36 U37 = TS5A23157: IC - TI TS5A23157 DUAL 10 OHM SPDT ANALOG SWITCH; IPN: H78521-001; Item Num: P01-13624R; Lead Free Status: Yes; Manufacturer: Texas Instruments; Manufacturer Part Num: TS5A23157DGSR; Num Pins: 10; Part Class: ICS; RoHS Compliant: Yes

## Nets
1.5V_DDR3: C436.1 C437.1 C450.1 C451.1 C452.1 C453.1 C454.1 C455.1 C456.1 C457.1 C458.1 C470.1 C471.1 C472.1 C473.1 C481.1 C482.1 C483.1 C484.1 C485.1 C486.1 C487.1 C494.1 C495.1 C497.1 C498.1 C500.1 C501.1 C509.1 C510.1 C511.1 C512.1 C513.1 C530.1 C531.1 C532.1 R287.2 R288.1 R339.2 U26.A1(VDDQ) U26.A8(VDDQ) U26.B2(VDD) U26.C1(VDDQ) U26.C9(VDDQ) U26.D2(VDDQ) U26.D9(VDD) U26.E9(VDDQ) U26.F1(VDDQ) U26.G7(VDD) U26.H2(VDDQ) U26.H9(VDDQ) U26.K2(VDD) U26.K8(VDD) U26.N1(VDD) U26.N9(VDD) U26.R1(VDD) U26.R9(VDD) U27.A1(VDDQ) U27.A8(VDDQ) U27.B2(VDD) U27.C1(VDDQ) U27.C9(VDDQ) U27.D2(VDDQ) U27.D9(VDD) U27.E9(VDDQ) U27.F1(VDDQ) U27.G7(VDD) U27.H2(VDDQ) U27.H9(VDDQ) U27.K2(VDD) U27.K8(VDD) U27.N1(VDD) U27.N9(VDD) U27.R1(VDD) U27.R9(VDD) U28.A1(VDDQ) U28.A8(VDDQ) U28.B2(VDD) U28.C1(VDDQ) U28.C9(VDDQ) U28.D2(VDDQ) U28.D9(VDD) U28.E9(VDDQ) U28.F1(VDDQ) U28.G7(VDD) U28.H2(VDDQ) U28.H9(VDDQ) U28.K2(VDD) U28.K8(VDD) U28.N1(VDD) U28.N9(VDD) U28.R1(VDD) U28.R9(VDD) ; also on sheet 13 14 27 29
1.8V: C103.1 C109.1 C491.1 C492.1 R324.1 U52.2(VDD) X6.4(VCC) ; also on sheet 14 15 19 20 21 26 29
2.5V: C8.1 C9.2 C134.1 C135.1 C145.1 C146.1 C147.1 C148.1 C161.2 C265.1 C319.1 J13.4 R117.2 R118.2 R119.2 R120.2 R121.2 R122.2 R157.1 R166.1 R175.1 R180.1 R182.1 R183.1 R186.2 R188.2 R190.1 R242.2 R281.2 R293.2 R319.1 R331.1 R332.1 R355.1 U3.2(VDD) U3.5(VDD) U3.9(VDD) U3.14(VDD) U3.17(VDD) U3.20(VDD) U3.27(VDD) U36.8(V+) U37.8(V+) X3.6(VDD) X4.6(VCC) X5.6(VCC) ; also on sheet 3 15 17 19 20 22 26 29
3.3V: R20.2 R25.2 ; also on sheet 14 16 18 19 20 21 23 24 25 26 27 28
GND: C8.2 C9.1 C97.2 C103.2 C109.2 C134.2 C135.2 C139.1 C140.2 C145.2 C146.2 C147.2 C148.2 C161.1 C265.2 C319.2 C436.2 C437.2 C450.2 C451.2 C452.2 C453.2 C454.2 C455.2 C456.2 C457.2 C458.2 C460.2 C470.2 C471.2 C472.2 C473.2 C481.2 C482.2 C483.2 C484.2 C485.2 C486.2 C487.2 C491.2 C492.2 C493.2 C494.2 C495.2 C496.2 C497.2 C498.2 C499.2 C500.2 C501.2 C509.2 C510.2 C511.2 C512.2 C513.2 C530.2 C531.2 C532.2 CN4.5 CN4.6 CN4.7 CN4.8 CN5.5 CN5.6 CN5.7 CN5.8 CN6.5 CN6.6 CN6.7 CN6.8 J3.2 J3.3 J3.4 J3.5 J4.2 J4.3 J4.4 J4.5 J6.2 J6.3 J6.4 J6.5 J7.2 J7.3 J7.4 J7.5 J13.10 J14.2 J14.3 J14.4 J14.5 R13.1 R19.2 R22.2 R23.2 R24.2 R98.1 R185.2 R187.2 R189.1 R286.2 R309.1 R325.2 R326.2 R327.2 R330.2 RN4.9(2) RN4.10(2) RN4.11(2) RN4.12(2) RN4.13(2) RN4.14(2) RN4.15(2) RN4.16(2) SW5.1(A1) SW5.2(A2) SW5.3(A3) SW5.4(A4) U3.22(NC) U3.29(GND) U13.AD17(CLK0p/FPLL_BL_FBp/DIFFIO_RX_B39p) U13.AE20(CLK3n/DIFFIO_RX_B63n) U26.A9(VSS) U26.B1(VSSQ) U26.B3(VSS) U26.B9(VSSQ) U26.D1(VSSQ) U26.D8(VSSQ) U26.E1(VSS) U26.E2(VSSQ) U26.E8(VSSQ) U26.F9(VSSQ) U26.G1(VSSQ) U26.G8(VSS) U26.G9(VSSQ) U26.J2(VSS) U26.J8(VSS) U26.M1(VSS) U26.M9(VSS) U26.P1(VSS) U26.P9(VSS) U26.T1(VSS) U26.T9(VSS) U27.A9(VSS) U27.B1(VSSQ) U27.B3(VSS) U27.B9(VSSQ) U27.D1(VSSQ) U27.D8(VSSQ) U27.E1(VSS) U27.E2(VSSQ) U27.E8(VSSQ) U27.F9(VSSQ) U27.G1(VSSQ) U27.G8(VSS) U27.G9(VSSQ) U27.J2(VSS) U27.J8(VSS) U27.M1(VSS) U27.M9(VSS) U27.P1(VSS) U27.P9(VSS) U27.T1(VSS) U27.T9(VSS) U28.A9(VSS) U28.B1(VSSQ) U28.B3(VSS) U28.B9(VSSQ) U28.D1(VSSQ) U28.D8(VSSQ) U28.E1(VSS) U28.E2(VSSQ) U28.E8(VSSQ) U28.F9(VSSQ) U28.G1(VSSQ) U28.G8(VSS) U28.G9(VSSQ) U28.J2(VSS) U28.J8(VSS) U28.M1(VSS) U28.M9(VSS) U28.P1(VSS) U28.P9(VSS) U28.T1(VSS) U28.T9(VSS) U36.3(GND) U37.3(GND) U52.1(GND) U52.5(OE3) X3.3(GND) X4.3(GND) X5.3(GND) X6.2(GND) ; also on sheet 3 4 6 7 13 14 15 16 17 18 19 20 21 22 23 24 25 26 27 28 29 30
100M_OSC_N: R12.2 U3.7(CLK1n) X4.5(CLK-)
100M_OSC_P: R12.1 U3.6(CLK1p) X4.4(CLK+)
BUFFER_EN: R13.2 U3.1(Gn)
C5_VCCIO_2.5V: R254.1 R255.1 R256.1 R269.1 ; also on sheet 22 26 29 30
CLK50_EN: R324.2 U52.6(OE1) U52.7(OE2) ; also on sheet 15
CLK125_EN: R242.1 X5.1(EN) ; also on sheet 15
CLK_125M_N: R245.2 U13.U30(CLK5n/DIFFIO_RX_R49n) X5.5(OUTn)
CLK_125M_P: R245.1 U13.U31(CLK5p/DIFFIO_RX_R49p) X5.4(OUT)
CLK_SEL: U3.28(CLK_SEL) ; also on sheet 15 20
CLKIN_50: U13.V28(CLK6p/DIFFIO_RX_R41p) U52.8(CLKOUT1)
CLKIN_MAX_50: U52.9(CLKOUT2) ; also on sheet 15
CLKIN_R_N: R251.2 U3.23(Q5n) U13.W27(CLK7n/FPLL_BR_FBn/DIFFIO_RX_R33n)
CLKIN_R_P: R251.1 U3.24(Q5p) U13.W26(CLK7p/FPLL_BR_FBp/DIFFIO_RX_R33p)
CLKIN_SMA_CN: C18.2 R19.1 R20.1 U3.15(CLK2n)
CLKIN_SMA_CP: C19.2 R24.1 R25.1 U3.16(CLK2p)
CLKIN_SMA_N: C18.1 J3.1 R22.1
CLKIN_SMA_P: C19.1 J6.1 R23.1
CLKINBOT_N: R266.2 U3.11(Q2n) U13.AG18(CLK2n/DIFFIO_RX_B55n)
CLKINBOT_P: R266.1 U3.10(Q2p) U13.AF18(CLK2p/DIFFIO_RX_B55p)
CLKINTOP_N: R181.2 U3.4(Q1n) U13.H18(CLK10n/DIFFIO_RX_T41n)
CLKINTOP_P: R181.1 U3.3(Q1p) U13.H19(CLK10p/DIFFIO_RX_T41p)
CLOCK_SCL: R175.2 X3.8(SCL) X4.8(SCL) ; also on sheet 15
CLOCK_SDA: R182.2 X3.7(SDA) X4.7(SDA) ; also on sheet 15
CPU_RESETn: U13.AD29(DEV_CLRn/DQ1R/DIFFIO_TX_R5n) ; also on sheet 15 20
DDR3A_A0: RN7.7 U26.N3(A0) U27.N3(A0) U28.N3(A0) ; also on sheet 4
DDR3A_A1: RN6.6 U26.P7(A1) U27.P7(A1) U28.P7(A1) ; also on sheet 4
DDR3A_A2: RN6.2 U13.AM18(DQ6B/HMC_B_A_2/FPLL_BL_CLKOUT0/FPLL_BL_CLKOUTp/FPLL_BL_FB/DIFFIO_TX_B45p) U26.P3(A2) U27.P3(A2) U28.P3(A2)
DDR3A_A3: RN7.3 U13.AN18(DQ6B/HMC_B_A_3/FPLL_BL_CLKOUT1/FPLL_BL_CLKOUTn/DIFFIO_TX_B45n) U26.N2(A3) U27.N2(A3) U28.N2(A3)
DDR3A_A4: RN5.4 U26.P8(A4) U27.P8(A4) U28.P8(A4) ; also on sheet 4
DDR3A_A5: RN7.6 U26.P2(A5) U27.P2(A5) U28.P2(A5) ; also on sheet 4
DDR3A_A6: RN5.3 U26.R8(A6) U27.R8(A6) U28.R8(A6) ; also on sheet 4
DDR3A_A7: RN7.5 U26.R2(A7) U27.R2(A7) U28.R2(A7) ; also on sheet 4
DDR3A_A8: RN6.7 U26.T8(A8) U27.T8(A8) U28.T8(A8) ; also on sheet 4
DDR3A_A9: RN7.8 U26.R3 (A9) U27.R3 (A9) U28.R3 (A9) ; also on sheet 4
DDR3A_A10: RN5.8 U26.L7(A10/AP) U27.L7(A10/AP) U28.L7(A10/AP) ; also on sheet 4
DDR3A_A11: RN6.5 U26.R7(A11) U27.R7(A11) U28.R7(A11) ; also on sheet 4
DDR3A_A12: RN5.2 U26.N7(A12/BCn) U27.N7(A12/BCn) U28.N7(A12/BCn) ; also on sheet 4
DDR3A_A13: RN6.1 U26.T3(A13) U27.T3(A13) U28.T3(A13) ; also on sheet 4
DDR3A_BA0: RN7.4 U26.M2(BA0) U27.M2(BA0) U28.M2(BA0) ; also on sheet 4
DDR3A_BA1: RN5.6 U26.N8(BA1) U27.N8(BA1) U28.N8(BA1) ; also on sheet 4
DDR3A_BA2: RN6.4 U26.M3(BA2) U27.M3(BA2) U28.M3(BA2) ; also on sheet 4
DDR3A_CASn: RN5.5 U26.K3(~{CAS}) U27.K3(~{CAS}) U28.K3(~{CAS}) ; also on sheet 4
DDR3A_CKE: R330.1 U26.K9(CKE) U27.K9(CKE) U28.K9(CKE) ; also on sheet 4
DDR3A_CLK_N: R317.1 R318.1 U26.K7(CK_N) U27.K7(CK_N) U28.K7(CK_N) ; also on sheet 4
DDR3A_CLK_P: R317.2 R318.2 U26.J7(CK_P) U27.J7(CK_P) U28.J7(CK_P) ; also on sheet 4
DDR3A_CSn: RN7.2 U26.L2(~{CS}) U27.L2(~{CS}) U28.L2(~{CS}) ; also on sheet 4
DDR3A_DM0: U26.E7(DM0) ; also on sheet 4
DDR3A_DM1: U26.D3(DM1) ; also on sheet 4
DDR3A_DM2: U27.E7(DM0) ; also on sheet 4
DDR3A_DM3: U27.D3(DM1) ; also on sheet 4
DDR3A_DM4: U28.E7(DM0) ; also on sheet 4
DDR3A_DQ0: U26.E3(DQ0) ; also on sheet 4
DDR3A_DQ1: U26.F7(DQ1) ; also on sheet 4
DDR3A_DQ2: U26.F2(DQ2) ; also on sheet 4
DDR3A_DQ3: U26.F8(DQ3) ; also on sheet 4
DDR3A_DQ4: U26.H3(DQ4) ; also on sheet 4
DDR3A_DQ5: U26.H8(DQ5) ; also on sheet 4
DDR3A_DQ6: U26.G2(DQ6) ; also on sheet 4
DDR3A_DQ7: U26.H7(DQ7) ; also on sheet 4
DDR3A_DQ8: U26.D7(DQ8) ; also on sheet 4
DDR3A_DQ9: U26.C3(DQ9) ; also on sheet 4
DDR3A_DQ10: U26.C8(DQ10) ; also on sheet 4
DDR3A_DQ11: U26.C2(DQ11) ; also on sheet 4
DDR3A_DQ12: U26.A7(DQ12) ; also on sheet 4
DDR3A_DQ13: U26.A2(DQ13) ; also on sheet 4
DDR3A_DQ14: U26.B8(DQ14) ; also on sheet 4
DDR3A_DQ15: U26.A3(DQ15) ; also on sheet 4
DDR3A_DQ16: U27.E3(DQ0) ; also on sheet 4
DDR3A_DQ17: U27.F7(DQ1) ; also on sheet 4
DDR3A_DQ18: U27.F2(DQ2) ; also on sheet 4
DDR3A_DQ19: U27.F8(DQ3) ; also on sheet 4
DDR3A_DQ20: U27.H3(DQ4) ; also on sheet 4
DDR3A_DQ21: U27.H8(DQ5) ; also on sheet 4
DDR3A_DQ22: U27.G2(DQ6) ; also on sheet 4
DDR3A_DQ23: U27.H7(DQ7) ; also on sheet 4
DDR3A_DQ24: U27.D7(DQ8) ; also on sheet 4
DDR3A_DQ25: U27.C3(DQ9) ; also on sheet 4
DDR3A_DQ26: U27.C8(DQ10) ; also on sheet 4
DDR3A_DQ27: U27.C2(DQ11) ; also on sheet 4
DDR3A_DQ28: U27.A7(DQ12) ; also on sheet 4
DDR3A_DQ29: U27.A2(DQ13) ; also on sheet 4
DDR3A_DQ30: U27.B8(DQ14) ; also on sheet 4
DDR3A_DQ31: U27.A3(DQ15) ; also on sheet 4
DDR3A_DQ32: U28.E3(DQ0) ; also on sheet 4
DDR3A_DQ33: U28.F7(DQ1) ; also on sheet 4
DDR3A_DQ34: U28.F2(DQ2) ; also on sheet 4
DDR3A_DQ35: U28.F8(DQ3) ; also on sheet 4
DDR3A_DQ36: U28.H3(DQ4) ; also on sheet 4
DDR3A_DQ37: U28.H8(DQ5) ; also on sheet 4
DDR3A_DQ38: U28.G2(DQ6) ; also on sheet 4
DDR3A_DQ39: U28.H7(DQ7) ; also on sheet 4
DDR3A_DQS_N0: U26.G3(DQS_N0) ; also on sheet 4
DDR3A_DQS_N1: U26.B7(DQS_N1) ; also on sheet 4
DDR3A_DQS_N2: U27.G3(DQS_N0) ; also on sheet 4
DDR3A_DQS_N3: U27.B7(DQS_N1) ; also on sheet 4
DDR3A_DQS_N4: U28.G3(DQS_N0) ; also on sheet 4
DDR3A_DQS_P0: U26.F3(DQS_P0) ; also on sheet 4
DDR3A_DQS_P1: U26.C7(DQS_P1) ; also on sheet 4
DDR3A_DQS_P2: U27.F3(DQS_P0) ; also on sheet 4
DDR3A_DQS_P3: U27.C7(DQS_P1) ; also on sheet 4
DDR3A_DQS_P4: U28.F3(DQS_P0) ; also on sheet 4
DDR3A_ODT: RN7.1 U26.K1(ODT) U27.K1(ODT) U28.K1(ODT) ; also on sheet 4
DDR3A_RASn: RN5.1 U26.J3(~{RAS}) U27.J3(~{RAS}) U28.J3(~{RAS}) ; also on sheet 4
DDR3A_RESETn: R339.1 U26.T2(RESETn) U27.T2(RESETn) U28.T2(RESETn) ; also on sheet 4
DDR3A_WEn: RN6.3 U26.L3(~{WE}) U27.L3(~{WE}) U28.L3(~{WE}) ; also on sheet 4
DDR3A_ZQ01: R327.1 U26.L8(ZQ)
DDR3A_ZQ02: R326.1 U27.L8(ZQ)
DDR3A_ZQ03: R325.1 U28.L8(ZQ)
DDR3B_A12: U13.T31(CLK4p/FPLL_TR_FBp/DIFFIO_RX_R57p) ; also on sheet 13
DDR3B_A13: U13.T30(CLK4n/FPLL_TR_FBn/DIFFIO_RX_R57n) ; also on sheet 13
DDR3B_CSn: U13.V27(CLK6n/DIFFIO_RX_R41n) ; also on sheet 13
DDR3B_DM3: U13.W34(DQ7R/FPLL_TR_CLKOUT1/FPLL_TR_CLKOUTn/DIFFIO_TX_R52n) ; also on sheet 13
DDR3B_DQ20: U13.AE33(DQ6R/FPLL_BR_CLKOUT1/FPLL_BR_CLKOUTn/DIFFIO_TX_R44n) ; also on sheet 13
FLASH_CEn: U13.AA21(nPERSTL0/DQS1R/DIFFIO_RX_R6p) ; also on sheet 14 15
FLASH_CLK: U13.AE29(DEV_OE/DIFFIO_TX_R5p) ; also on sheet 14 15
FLASH_RDYBSYn: U13.AD20(CLK3p/DIFFIO_RX_B63p) ; also on sheet 14 15
FM_A2: U13.AC27(nCEO/DQ1R/DIFFIO_TX_R3p) ; also on sheet 14 15
FM_D13: U13.AC24(CRC_ERROR/DIFFIO_RX_R2n) ; also on sheet 14 15
FM_D15: U13.AC23(INIT_DONE/DIFFIO_RX_R2p) ; also on sheet 14 15
FORCE_FAN: R122.1 SW5.5(B4) ; also on sheet 15
FPGA_CEn: R189.2 R190.2 U13.F7(nCE) ; also on sheet 15
FPGA_CONF_DONE: R331.2 U13.G10(CONF_DONE) ; also on sheet 15
FPGA_CONFIG_D0: U13.AH9(AS_DATA0/ASDO) ; also on sheet 14 15
FPGA_CONFIG_D1: U13.AJ7(AS_DATA1) ; also on sheet 14 15
FPGA_CONFIG_D2: U13.AH8(AS_DATA2) ; also on sheet 14 15
FPGA_CONFIG_D3: U13.AJ6(AS_DATA3) ; also on sheet 14 15
FPGA_CONFIG_D4: U13.AG10(DATA4/nCSO) ; also on sheet 14 15
FPGA_CONFIG_D5: U13.AM4(DATA5/DIFFIO_TX_B2n) ; also on sheet 15
FPGA_CONFIG_D6: U13.AD11(DATA6/DQ1B/DIFFIO_RX_B1n) ; also on sheet 15
FPGA_CONFIG_D7: U13.AM5(DATA7/DQ1B/DIFFIO_TX_B2p) ; also on sheet 15
FPGA_CONFIG_D8: U13.AD12(DATA8/DQ1B/DIFFIO_RX_B1p) ; also on sheet 15
FPGA_CONFIG_D9: U13.AL7(DATA9/DQ1B/DIFFIO_TX_B4n) ; also on sheet 15
FPGA_CONFIG_D10: U13.AJ11(DATA10/DQSn1B/DIFFIO_RX_B3n) ; also on sheet 15
FPGA_CONFIG_D11: U13.AK7(DATA11/DIFFIO_TX_B4p) ; also on sheet 15
FPGA_CONFIG_D12: U13.AH12(DATA12/DQS1B/DIFFIO_RX_B3p) ; also on sheet 15
FPGA_CONFIG_D13: U13.AL8(DATA13/DQ1B/DIFFIO_TX_B6n) ; also on sheet 15
FPGA_CONFIG_D14: U13.AG13(DATA14/DQ1B/DIFFIO_RX_B5n) ; also on sheet 15
FPGA_CONFIG_D15: U13.AK8(DATA15/DQ1B/DIFFIO_TX_B6p) ; also on sheet 15
FPGA_CvP_CONFDONE: R255.2 U13.AC26(CvP_CONFDONE/DQ1R/DIFFIO_TX_R3n) ; also on sheet 15
FPGA_DCLK: R97.1 R98.2 U13.AF10(DCLK) ; also on sheet 14 15
FPGA_MSEL0: R185.1 R186.1 U13.J12(MSEL0) ; also on sheet 15
FPGA_MSEL1: R119.1 SW5.8(B1) U13.J11(MSEL1) ; also on sheet 15
FPGA_MSEL2: R120.1 SW5.7(B2) U13.F6(MSEL2) ; also on sheet 15
FPGA_MSEL3: R187.1 R188.1 U13.K10(MSEL3) ; also on sheet 15
FPGA_MSEL4: R121.1 SW5.6(B3) U13.H7(MSEL4) ; also on sheet 15
FPGA_nCONFIG: R355.2 U13.G8(nCONFIG) ; also on sheet 15
FPGA_nSTATUS: R332.2 U13.G9(nSTATUS) ; also on sheet 15
FPGA_PR_DONE: U13.AC12(PR_DONE/DIFFIO_RX_B7n) ; also on sheet 15
FPGA_PR_ERROR: R256.2 U13.AC13(PR_ERROR/DIFFIO_RX_B7p) ; also on sheet 15
FPGA_PR_READY: R269.2 U13.AK9(PR_READY/DQ1B/DIFFIO_TX_B8n) ; also on sheet 15
FPGA_PR_REQUEST: R254.2 U13.AD25(PR_REQUEST/DQ1R/DIFFIO_TX_R1n) ; also on sheet 15
GL: R166.2 U3.8(GL)
HSMA_CLK_IN_N1: R217.2 U13.F18(CLK9n/DIFFIO_RX_T49n) ; also on sheet 18
HSMA_CLK_IN_N2: R218.2 U13.H16(CLK8n/FPLL_TL_FBn/DIFFIO_RX_T57n) ; also on sheet 18
HSMA_CLK_IN_P1: R217.1 U13.G18(CLK9p/DIFFIO_RX_T49p) ; also on sheet 18
HSMA_CLK_IN_P2: R218.1 U13.H17(CLK8p/FPLL_TL_FBp/DIFFIO_RX_T57p) ; also on sheet 18
HSMA_CLK_OUT_N2: U13.A18(DQ7T/HMC_T_A_3/FPLL_TL_CLKOUT1/FPLL_TL_CLKOUTn/DIFFIO_TX_T52n) ; also on sheet 18
HSMA_CLK_OUT_P2: U13.B18(DQ7T/HMC_T_A_2/FPLL_TL_CLKOUT0/FPLL_TL_CLKOUTp/FPLL_TL_FB/DIFFIO_TX_T52p) ; also on sheet 18
HSMA_JTAG_EN: U36.1(IN1) U36.5(IN2) ; also on sheet 3
HSMA_JTAG_TDO: U36.2(NO1) ; also on sheet 18
HSMA_JTAG_TMS: U36.6(COM2) ; also on sheet 18
HSMB_CLK_IN_N2: R223.2 U13.K19(CLK11n/DIFFIO_RX_T33n) ; also on sheet 18
HSMB_CLK_IN_P2: R223.1 U13.J20(CLK11p/DIFFIO_RX_T33p) ; also on sheet 18
HSMB_JTAG_EN: U37.1(IN1) U37.5(IN2) ; also on sheet 3
HSMB_JTAG_TDI: U36.10(COM1) U37.9(NC1) ; also on sheet 18
HSMB_JTAG_TDO: U37.2(NO1) ; also on sheet 18
HSMB_JTAG_TMS: U37.6(COM2) ; also on sheet 18
JTAG_BLASTER_TDI: J13.3 R285.2 ; also on sheet 15 19
JTAG_BLASTER_TDO: J13.9 R258.2 R281.1 R285.1 U13.AE10(TDI) ; also on sheet 19
JTAG_EPM2210_TDI: U37.10(COM1) ; also on sheet 15
JTAG_FPGA_TDO: R258.1 U13.AF11(TDO) U36.9(NC1) ; also on sheet 18
JTAG_TCK: J13.1 R308.1 R309.2 U13.AK5(TCK) ; also on sheet 15 18 19
JTAG_TMS: J13.5 R293.1 U13.AG11(TMS) U36.4(NO2) U37.4(NO2) ; also on sheet 15 19
MAX_CLK: U13.Y34(DQ7R/FPLL_TR_CLKOUT0/FPLL_TR_CLKOUTp/FPLL_TR_FB/DIFFIO_TX_R52p) ; also on sheet 15
PCIE_PERSTn: U13.AA22(nPERSTL1/DQSn1R/DIFFIO_RX_R6n) ; also on sheet 3
PDn: R180.2 U3.21(PDn)
REFCLK_QL1_CN: C20.1 U3.13(Q3n)
REFCLK_QL1_CP: C15.1 U3.12(Q3p)
REFCLK_QL1_N: C20.2 ; also on sheet 7
REFCLK_QL1_P: C15.2 ; also on sheet 7
REFCLK_QL2_CN: C155.1 X3.5(CLK-)
REFCLK_QL2_CP: C154.1 X3.4(CLK+)
REFCLK_QL2_N: C155.2 ; also on sheet 7
REFCLK_QL2_P: C154.2 ; also on sheet 7
REFCLK_QL3_CN: C160.1 U3.18(Q4n)
REFCLK_QL3_CP: C159.1 U3.19(Q4p)
REFCLK_QL3_N: C160.2 ; also on sheet 7
REFCLK_QL3_P: C159.2 ; also on sheet 7
SDI_CLK148_DN: R159.2 ; also on sheet 5
SDI_CLK148_UP: R158.2 ; also on sheet 5
SI570_EN: R183.2 X4.2(OE) ; also on sheet 15
SI571_EN: R157.2 X3.2(OE) ; also on sheet 15
SI571_VCONTROL: C139.2 R158.1 R159.1 R160.1 X3.1(VC)
SMA_CLKOUT: J14.1 U13.AF33(DQ6R/FPLL_BR_CLKOUT0/FPLL_BR_CLKOUTp/FPLL_BR_FB/DIFFIO_TX_R44p)
SMA_CLKOUT_N: J7.1 U3.25(Q6n)
SMA_CLKOUT_P: J4.1 U3.26(Q6p)
USB_CLK: U13.AC18(CLK1p/DIFFIO_RX_B47p) ; also on sheet 15 19
USB_DISABLEn: J13.2 R319.2 ; also on sheet 19
USB_RDn: U13.AB18(CLK1n/DIFFIO_RX_B47n) ; also on sheet 19
USB_RESETn: U13.AC17(CLK0n/FPLL_BL_FBn/DIFFIO_RX_B39n) ; also on sheet 19
VREF_DDR3A: C493.1 C496.1 C499.1 U26.H1(VREFDQ) U26.M8(VREFCA) U27.H1(VREFDQ) U27.M8(VREFCA) U28.H1(VREFDQ) U28.M8(VREFCA) ; also on sheet 22 27 30
VTT_DDR3A: CN4.1 CN4.2 CN4.3 CN4.4 CN5.1 CN5.2 CN5.3 CN5.4 CN6.1 CN6.2 CN6.3 CN6.4 RN5.9(2) RN5.10(2) RN5.11(2) RN5.12(2) RN5.13(2) RN5.14(2) RN5.15(2) RN5.16(2) RN6.9(2) RN6.10(2) RN6.11(2) RN6.12(2) RN6.13(2) RN6.14(2) RN6.15(2) RN6.16(2) RN7.9(2) RN7.10(2) RN7.11(2) RN7.12(2) RN7.13(2) RN7.14(2) RN7.15(2) RN7.16(2) ; also on sheet 27
N93449833: C460.1 R308.2
N107481162: R117.1 U36.7(NC2)
N107646358: R118.1 U37.7(NC2)
N126408835: C97.1 R97.2
N126463592: R286.1 U28.C7(DQS_P1)
N126463602: R287.1 U28.B7(DQS_N1)
N126463913: RN4.2 U28.D7(DQ8)
N126467340: RN4.4 U28.C8(DQ10)
N126467588: RN4.5 U28.C2(DQ11)
N126467837: RN4.6 U28.A7(DQ12)
N126468087: RN4.7 U28.A2(DQ13)
N126468338: RN4.1 U28.B8(DQ14)
N126468590: RN4.8 U28.A3(DQ15)
N126468843: RN4.3 U28.C3(DQ9)
N126473632: R288.2 U28.D3(DM1)
N126489077: C140.1 R160.2
N126489144: U52.4(OE_OSC) X6.1(EN)
N126489190: U52.3(CLKIN) X6.3(OUT)

Not connected (* = marked no-connect by the designer): J13 6* 7* 8*; RN5 7*; RN6 8*; U13 AF13(CLKUSR/DQ1B/DIFFIO_RX_B5p) AJ9(IO/DQ1B/DIFFIO_TX_B8p)*; U26 J1(NC1)* J9(NC2)* L1(NC3)* L9(NC4)* M7(NC5)* T7(NC6)*; U27 J1(NC1)* J9(NC2)* L1(NC3)* L9(NC4)* M7(NC5)* T7(NC6)*; U28 J1(NC1)* J9(NC2)* L1(NC3)* L9(NC4)* M7(NC5)* T7(NC6)*; U52 10(CLKOUT3)*; X4 1(NC)*; X5 2(NC)*

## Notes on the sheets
sheet 8
- Clocks/Oscillators
- Si570 Programmable Oscillator
  Use Clock Control GUI
  (Default 100MHz)
  I2C Address 00 HEX
- CLK_SEL =  HIGH selects (CLK1p/n) Si570 input
  CLK_SEL =  LOW selects (CLK2p/n) SMA input
- Si571 Programmable Oscillator
  Use Clock Control GUI
  (Default 148.5MHz)
  I2C Address 55 HEX
- From FPGA
sheet 9
- Cyclone V GT Clocks
- CLOCKS
- DOES NOT NEED TO BE A CLOCK OUT,
  CAN BE USED AS I/O.
- VCCIO = 1.5V
- HSMC PORT A INTERFACE
- VCCIO = 1.5V
- HSMC PORT B INTERFACE
- VCCIO = 1.5V
- USB INTERFACE
- VCCIO = 1.5V
- DDR3A x40 HMC INTERFACE
- DDR3B X64 SMC INTERFACE
- VCCIO = VARIES
- VCCIO = 2.5V
- FLASH INTERFACE
sheet 10
- Cyclone V GT Configuration
- INSTALL THIS RESISTOR ONLY WHEN FPGA IS NOT POPULATED.
- FLASH INTERFACE
sheet 11
- JTAG
- TS5A23157 Switch Functions
- When Pins 1 & 5 are:
  LOW --> NC to/from COM  = ON and NO to/from COM = OFF
  HIGH --> NC to/from COM = OFF and NO to/from COM = ON
- Logic 0 = pin 10 <--> pin 9 (HSMB Bypass)
  Logic 1 = pin 10 <--> pin 2 (HSMB Enable)
- USB Blaster Programming Header
- (uses JTAG mode only)
- Logic 0 = pin 6 <--> pin 7 (HSMBBypass)
  Logic 1 = pin 6 <--> pin 4 (HSMB Enable)
- Logic 0 = pin 10 <--> pin 9 (HSMA Bypass)
  Logic 1 = pin 10 <--> pin 2 (HSMA Enable)
- Populate R285 if you would like to
  Master the JTAG chain through
  HSMC Port A or HSMC Port B
- Logic 0 = pin 6 <--> pin 7 (HSMA Bypass)
  Logic 1 = pin 6 <--> pin 4 (HSMA Enable)
sheet 12
- DDR3A (x40 HMC)
- Uses Hard Memory Controller
- Place one termination resistor at
  the end of each branch.
- Place These Caps Near DDR3
  (U26,  U27, and U28)
